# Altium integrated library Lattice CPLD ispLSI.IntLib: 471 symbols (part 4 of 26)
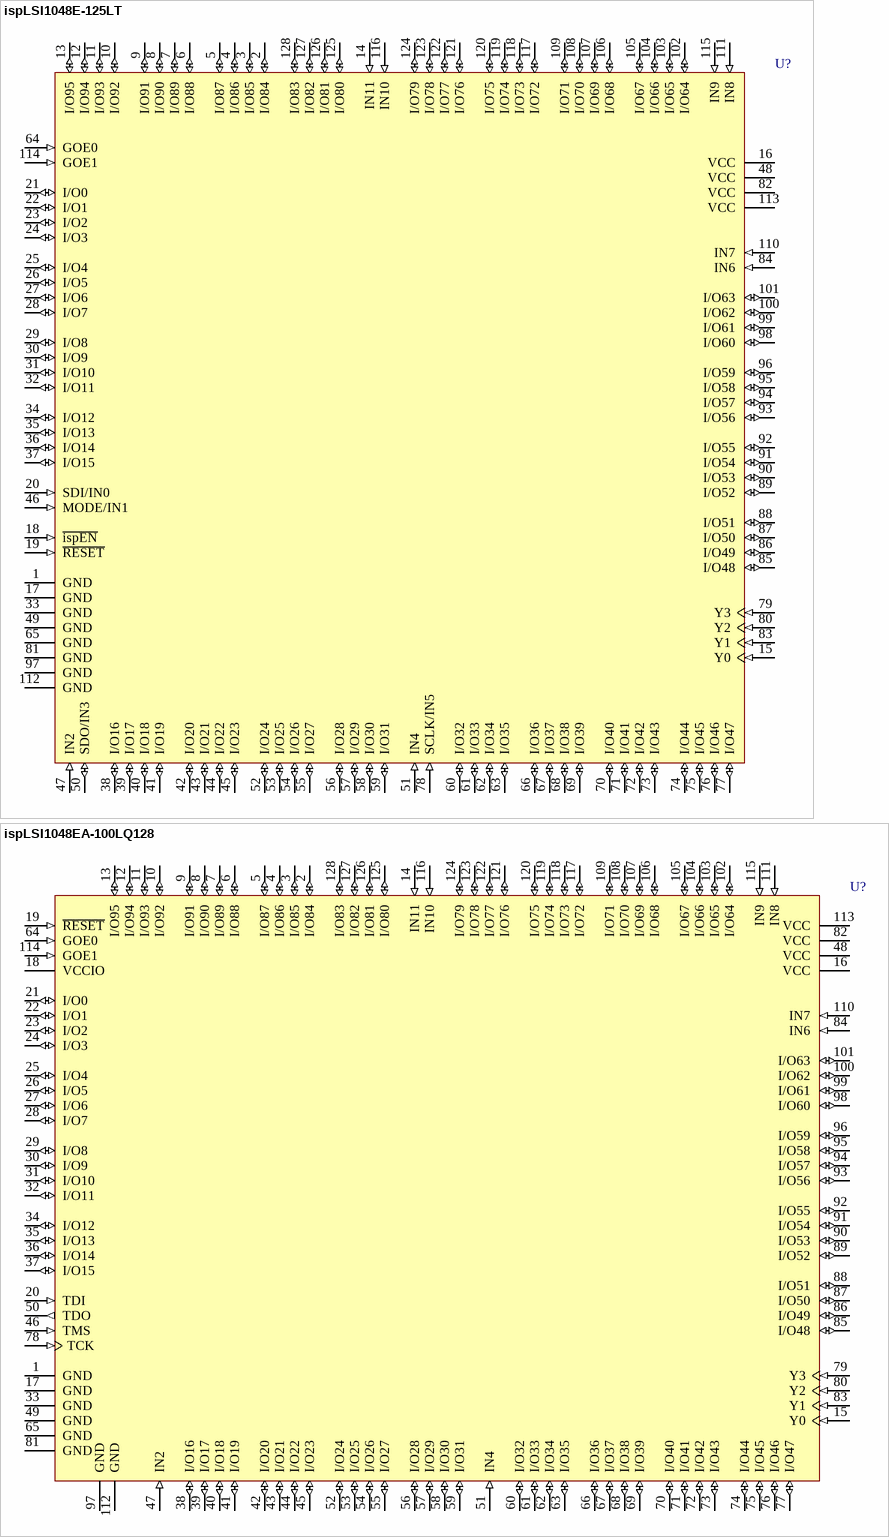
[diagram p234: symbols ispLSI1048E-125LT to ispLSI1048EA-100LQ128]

## ispLSI1048EA-100LQ128
designator U?
In-System Programmable High-Density PLD
footprint PQFP128_N (QFP, 128-Leads, Body 28x28mm, Pitch 0.8mm, IPC Medium Density)
footprint PQFP128_L (QFP, 128-Leads, Body 28x28mm, Pitch 0.8mm, IPC High Density)
footprint PQFP128_M (QFP, 128-Leads, Body 28x28mm, Pitch 0.8mm, IPC Low Density)
3D model 1048EA-PQFP128 (128-Pin Quad Flat Pack 0.8 mm Pitch)
pins: 1 GND (power), 2 I/O84 (io), 3 I/O85 (io), 4 I/O86 (io), 5 I/O87 (io), 6 I/O88 (io), 7 I/O89 (io), 8 I/O90 (io), 9 I/O91 (io), 10 I/O92 (io), 11 I/O93 (io), 12 I/O94 (io), 13 I/O95 (io), 14 IN11 (in), 15 Y0 (in), 16 VCC (power), 17 GND (power), 18 VCCIO (power), 19 ~{RESET} (in), 20 TDI (in), 21 I/O0 (io), 22 I/O1 (io), 23 I/O2 (io), 24 I/O3 (io), 25 I/O4 (io), 26 I/O5 (io), 27 I/O6 (io), 28 I/O7 (io), 29 I/O8 (io), 30 I/O9 (io), 31 I/O10 (io), 32 I/O11 (io), 33 GND (power), 34 I/O12 (io), 35 I/O13 (io), 36 I/O14 (io), 37 I/O15 (io), 38 I/O16 (io), 39 I/O17 (io), 40 I/O18 (io), 41 I/O19 (io), 42 I/O20 (io), 43 I/O21 (io), 44 I/O22 (io), 45 I/O23 (io), 46 TMS (in), 47 IN2 (in), 48 VCC (power), 49 GND (power), 50 TDO (out), 51 IN4 (in), 52 I/O24 (io), 53 I/O25 (io), 54 I/O26 (io), 55 I/O27 (io), 56 I/O28 (io), 57 I/O29 (io), 58 I/O30 (io), 59 I/O31 (io), 60 I/O32 (io), 61 I/O33 (io), 62 I/O34 (io), 63 I/O35 (io), 64 GOE0 (in), 65 GND (power), 66 I/O36 (io), 67 I/O37 (io), 68 I/O38 (io), 69 I/O39 (io), 70 I/O40 (io), 71 I/O41 (io), 72 I/O42 (io), 73 I/O43 (io), 74 I/O44 (io), 75 I/O45 (io), 76 I/O46 (io), 77 I/O47 (io), 78 TCK (in), 79 Y3 (in), 80 Y2 (in), 81 GND (power), 82 VCC (power), 83 Y1 (in), 84 IN6 (in), 85 I/O48 (io), 86 I/O49 (io), 87 I/O50 (io), 88 I/O51 (io), 89 I/O52 (io), 90 I/O53 (io), 91 I/O54 (io), 92 I/O55 (io), 93 I/O56 (io), 94 I/O57 (io), 95 I/O58 (io), 96 I/O59 (io), 97 GND (power), 98 I/O60 (io), 99 I/O61 (io), 100 I/O62 (io), 101 I/O63 (io), 102 I/O64 (io), 103 I/O65 (io), 104 I/O66 (io), 105 I/O67 (io), 106 I/O68 (io), 107 I/O69 (io), 108 I/O70 (io), 109 I/O71 (io), 110 IN7 (in), 111 IN8 (in), 112 GND (power), 113 VCC (power), 114 GOE1 (in), 115 IN9 (in), 116 IN10 (in), 117 I/O72 (io), 118 I/O73 (io), 119 I/O74 (io), 120 I/O75 (io), 121 I/O76 (io), 122 I/O77 (io), 123 I/O78 (io), 124 I/O79 (io), 125 I/O80 (io), 126 I/O81 (io), 127 I/O82 (io), 128 I/O83 (io)

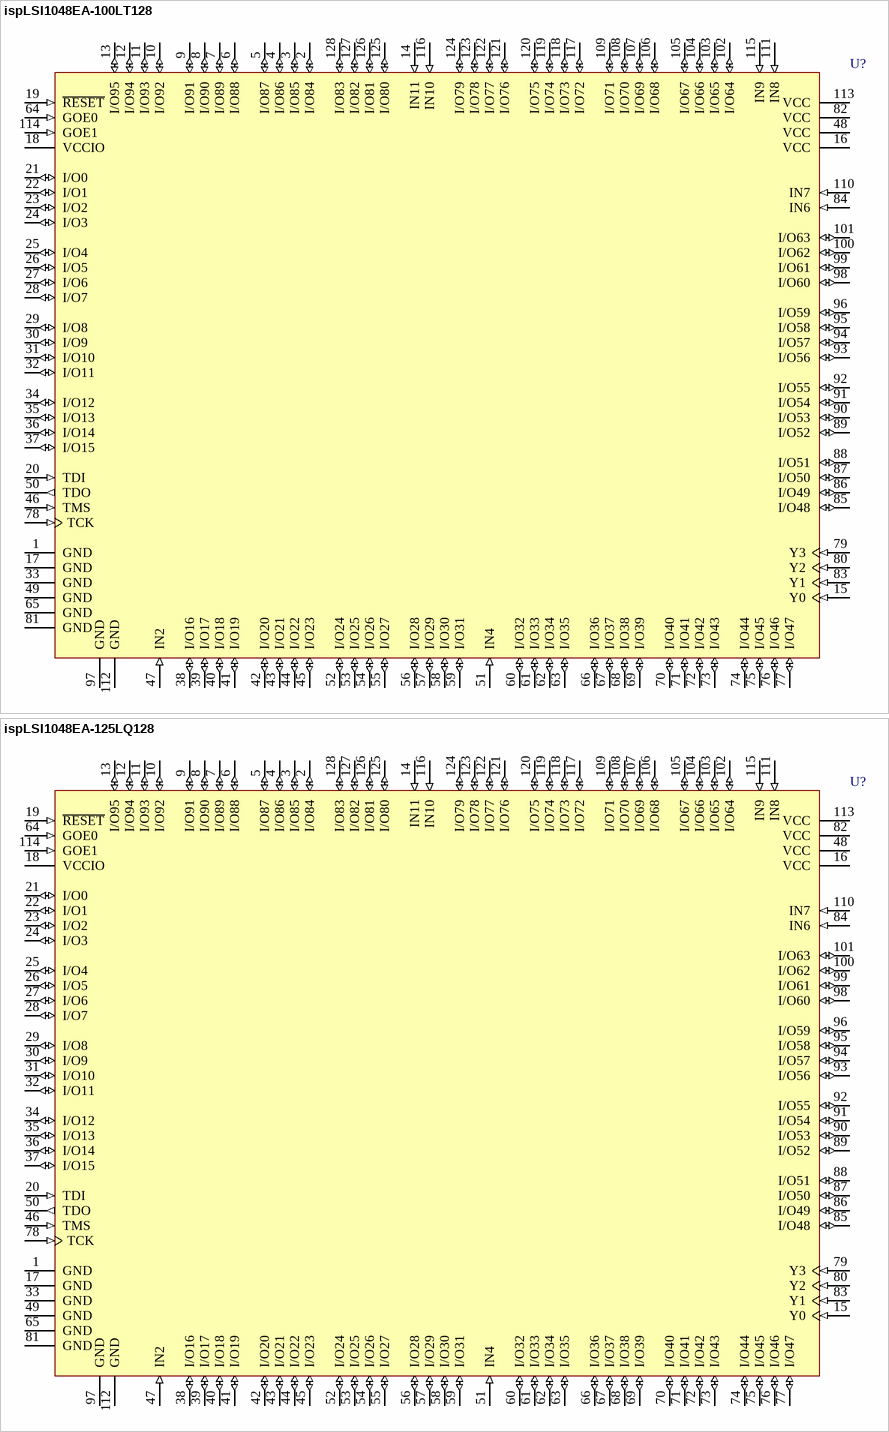
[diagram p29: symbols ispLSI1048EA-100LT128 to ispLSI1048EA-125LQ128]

## ispLSI1048EA-100LT128
designator U?
In-System Programmable High-Density PLD
footprint TQFP128_N (Thin QFP, 128-Leads, Body 14x14mm, Pitch 0.4mm, IPC Medium Density)
footprint TQFP128_L (Thin QFP, 128-Leads, Body 14x14mm, Pitch 0.4mm, IPC High Density)
footprint TQFP128_M (Thin QFP, 128-Leads, Body 14x14mm, Pitch 0.4mm, IPC Low Density)
3D model 1048EA-TQFP128 (128-Pin Thin Quad Flat Pack 0.4 mm Pitch)
pins: 1 GND (power), 2 I/O84 (io), 3 I/O85 (io), 4 I/O86 (io), 5 I/O87 (io), 6 I/O88 (io), 7 I/O89 (io), 8 I/O90 (io), 9 I/O91 (io), 10 I/O92 (io), 11 I/O93 (io), 12 I/O94 (io), 13 I/O95 (io), 14 IN11 (in), 15 Y0 (in), 16 VCC (power), 17 GND (power), 18 VCCIO (power), 19 ~{RESET} (in), 20 TDI (in), 21 I/O0 (io), 22 I/O1 (io), 23 I/O2 (io), 24 I/O3 (io), 25 I/O4 (io), 26 I/O5 (io), 27 I/O6 (io), 28 I/O7 (io), 29 I/O8 (io), 30 I/O9 (io), 31 I/O10 (io), 32 I/O11 (io), 33 GND (power), 34 I/O12 (io), 35 I/O13 (io), 36 I/O14 (io), 37 I/O15 (io), 38 I/O16 (io), 39 I/O17 (io), 40 I/O18 (io), 41 I/O19 (io), 42 I/O20 (io), 43 I/O21 (io), 44 I/O22 (io), 45 I/O23 (io), 46 TMS (in), 47 IN2 (in), 48 VCC (power), 49 GND (power), 50 TDO (out), 51 IN4 (in), 52 I/O24 (io), 53 I/O25 (io), 54 I/O26 (io), 55 I/O27 (io), 56 I/O28 (io), 57 I/O29 (io), 58 I/O30 (io), 59 I/O31 (io), 60 I/O32 (io), 61 I/O33 (io), 62 I/O34 (io), 63 I/O35 (io), 64 GOE0 (in), 65 GND (power), 66 I/O36 (io), 67 I/O37 (io), 68 I/O38 (io), 69 I/O39 (io), 70 I/O40 (io), 71 I/O41 (io), 72 I/O42 (io), 73 I/O43 (io), 74 I/O44 (io), 75 I/O45 (io), 76 I/O46 (io), 77 I/O47 (io), 78 TCK (in), 79 Y3 (in), 80 Y2 (in), 81 GND (power), 82 VCC (power), 83 Y1 (in), 84 IN6 (in), 85 I/O48 (io), 86 I/O49 (io), 87 I/O50 (io), 88 I/O51 (io), 89 I/O52 (io), 90 I/O53 (io), 91 I/O54 (io), 92 I/O55 (io), 93 I/O56 (io), 94 I/O57 (io), 95 I/O58 (io), 96 I/O59 (io), 97 GND (power), 98 I/O60 (io), 99 I/O61 (io), 100 I/O62 (io), 101 I/O63 (io), 102 I/O64 (io), 103 I/O65 (io), 104 I/O66 (io), 105 I/O67 (io), 106 I/O68 (io), 107 I/O69 (io), 108 I/O70 (io), 109 I/O71 (io), 110 IN7 (in), 111 IN8 (in), 112 GND (power), 113 VCC (power), 114 GOE1 (in), 115 IN9 (in), 116 IN10 (in), 117 I/O72 (io), 118 I/O73 (io), 119 I/O74 (io), 120 I/O75 (io), 121 I/O76 (io), 122 I/O77 (io), 123 I/O78 (io), 124 I/O79 (io), 125 I/O80 (io), 126 I/O81 (io), 127 I/O82 (io), 128 I/O83 (io)

## ispLSI1048EA-125LQ128
designator U?
In-System Programmable High-Density PLD
footprint PQFP128_N (QFP, 128-Leads, Body 28x28mm, Pitch 0.8mm, IPC Medium Density)
footprint PQFP128_L (QFP, 128-Leads, Body 28x28mm, Pitch 0.8mm, IPC High Density)
footprint PQFP128_M (QFP, 128-Leads, Body 28x28mm, Pitch 0.8mm, IPC Low Density)
3D model 1048EA-PQFP128 (128-Pin Quad Flat Pack 0.8 mm Pitch)
pins: 1 GND (power), 2 I/O84 (io), 3 I/O85 (io), 4 I/O86 (io), 5 I/O87 (io), 6 I/O88 (io), 7 I/O89 (io), 8 I/O90 (io), 9 I/O91 (io), 10 I/O92 (io), 11 I/O93 (io), 12 I/O94 (io), 13 I/O95 (io), 14 IN11 (in), 15 Y0 (in), 16 VCC (power), 17 GND (power), 18 VCCIO (power), 19 ~{RESET} (in), 20 TDI (in), 21 I/O0 (io), 22 I/O1 (io), 23 I/O2 (io), 24 I/O3 (io), 25 I/O4 (io), 26 I/O5 (io), 27 I/O6 (io), 28 I/O7 (io), 29 I/O8 (io), 30 I/O9 (io), 31 I/O10 (io), 32 I/O11 (io), 33 GND (power), 34 I/O12 (io), 35 I/O13 (io), 36 I/O14 (io), 37 I/O15 (io), 38 I/O16 (io), 39 I/O17 (io), 40 I/O18 (io), 41 I/O19 (io), 42 I/O20 (io), 43 I/O21 (io), 44 I/O22 (io), 45 I/O23 (io), 46 TMS (in), 47 IN2 (in), 48 VCC (power), 49 GND (power), 50 TDO (out), 51 IN4 (in), 52 I/O24 (io), 53 I/O25 (io), 54 I/O26 (io), 55 I/O27 (io), 56 I/O28 (io), 57 I/O29 (io), 58 I/O30 (io), 59 I/O31 (io), 60 I/O32 (io), 61 I/O33 (io), 62 I/O34 (io), 63 I/O35 (io), 64 GOE0 (in), 65 GND (power), 66 I/O36 (io), 67 I/O37 (io), 68 I/O38 (io), 69 I/O39 (io), 70 I/O40 (io), 71 I/O41 (io), 72 I/O42 (io), 73 I/O43 (io), 74 I/O44 (io), 75 I/O45 (io), 76 I/O46 (io), 77 I/O47 (io), 78 TCK (in), 79 Y3 (in), 80 Y2 (in), 81 GND (power), 82 VCC (power), 83 Y1 (in), 84 IN6 (in), 85 I/O48 (io), 86 I/O49 (io), 87 I/O50 (io), 88 I/O51 (io), 89 I/O52 (io), 90 I/O53 (io), 91 I/O54 (io), 92 I/O55 (io), 93 I/O56 (io), 94 I/O57 (io), 95 I/O58 (io), 96 I/O59 (io), 97 GND (power), 98 I/O60 (io), 99 I/O61 (io), 100 I/O62 (io), 101 I/O63 (io), 102 I/O64 (io), 103 I/O65 (io), 104 I/O66 (io), 105 I/O67 (io), 106 I/O68 (io), 107 I/O69 (io), 108 I/O70 (io), 109 I/O71 (io), 110 IN7 (in), 111 IN8 (in), 112 GND (power), 113 VCC (power), 114 GOE1 (in), 115 IN9 (in), 116 IN10 (in), 117 I/O72 (io), 118 I/O73 (io), 119 I/O74 (io), 120 I/O75 (io), 121 I/O76 (io), 122 I/O77 (io), 123 I/O78 (io), 124 I/O79 (io), 125 I/O80 (io), 126 I/O81 (io), 127 I/O82 (io), 128 I/O83 (io)

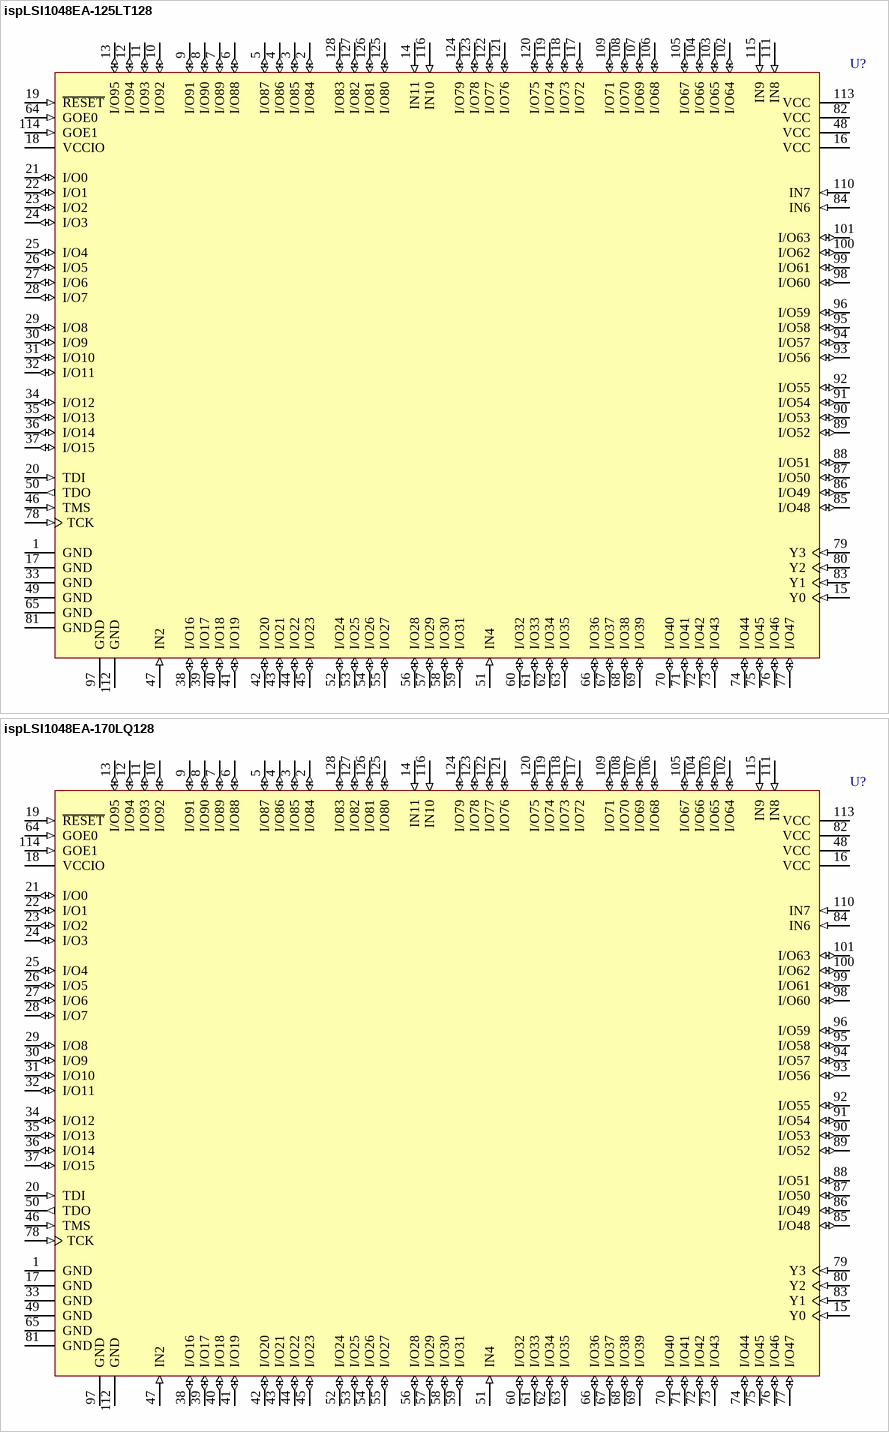
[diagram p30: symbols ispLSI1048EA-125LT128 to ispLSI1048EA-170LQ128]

## ispLSI1048EA-125LT128
designator U?
In-System Programmable High-Density PLD
footprint TQFP128_N (Thin QFP, 128-Leads, Body 14x14mm, Pitch 0.4mm, IPC Medium Density)
footprint TQFP128_L (Thin QFP, 128-Leads, Body 14x14mm, Pitch 0.4mm, IPC High Density)
footprint TQFP128_M (Thin QFP, 128-Leads, Body 14x14mm, Pitch 0.4mm, IPC Low Density)
3D model 1048EA-TQFP128 (128-Pin Thin Quad Flat Pack 0.4 mm Pitch)
pins: 1 GND (power), 2 I/O84 (io), 3 I/O85 (io), 4 I/O86 (io), 5 I/O87 (io), 6 I/O88 (io), 7 I/O89 (io), 8 I/O90 (io), 9 I/O91 (io), 10 I/O92 (io), 11 I/O93 (io), 12 I/O94 (io), 13 I/O95 (io), 14 IN11 (in), 15 Y0 (in), 16 VCC (power), 17 GND (power), 18 VCCIO (power), 19 ~{RESET} (in), 20 TDI (in), 21 I/O0 (io), 22 I/O1 (io), 23 I/O2 (io), 24 I/O3 (io), 25 I/O4 (io), 26 I/O5 (io), 27 I/O6 (io), 28 I/O7 (io), 29 I/O8 (io), 30 I/O9 (io), 31 I/O10 (io), 32 I/O11 (io), 33 GND (power), 34 I/O12 (io), 35 I/O13 (io), 36 I/O14 (io), 37 I/O15 (io), 38 I/O16 (io), 39 I/O17 (io), 40 I/O18 (io), 41 I/O19 (io), 42 I/O20 (io), 43 I/O21 (io), 44 I/O22 (io), 45 I/O23 (io), 46 TMS (in), 47 IN2 (in), 48 VCC (power), 49 GND (power), 50 TDO (out), 51 IN4 (in), 52 I/O24 (io), 53 I/O25 (io), 54 I/O26 (io), 55 I/O27 (io), 56 I/O28 (io), 57 I/O29 (io), 58 I/O30 (io), 59 I/O31 (io), 60 I/O32 (io), 61 I/O33 (io), 62 I/O34 (io), 63 I/O35 (io), 64 GOE0 (in), 65 GND (power), 66 I/O36 (io), 67 I/O37 (io), 68 I/O38 (io), 69 I/O39 (io), 70 I/O40 (io), 71 I/O41 (io), 72 I/O42 (io), 73 I/O43 (io), 74 I/O44 (io), 75 I/O45 (io), 76 I/O46 (io), 77 I/O47 (io), 78 TCK (in), 79 Y3 (in), 80 Y2 (in), 81 GND (power), 82 VCC (power), 83 Y1 (in), 84 IN6 (in), 85 I/O48 (io), 86 I/O49 (io), 87 I/O50 (io), 88 I/O51 (io), 89 I/O52 (io), 90 I/O53 (io), 91 I/O54 (io), 92 I/O55 (io), 93 I/O56 (io), 94 I/O57 (io), 95 I/O58 (io), 96 I/O59 (io), 97 GND (power), 98 I/O60 (io), 99 I/O61 (io), 100 I/O62 (io), 101 I/O63 (io), 102 I/O64 (io), 103 I/O65 (io), 104 I/O66 (io), 105 I/O67 (io), 106 I/O68 (io), 107 I/O69 (io), 108 I/O70 (io), 109 I/O71 (io), 110 IN7 (in), 111 IN8 (in), 112 GND (power), 113 VCC (power), 114 GOE1 (in), 115 IN9 (in), 116 IN10 (in), 117 I/O72 (io), 118 I/O73 (io), 119 I/O74 (io), 120 I/O75 (io), 121 I/O76 (io), 122 I/O77 (io), 123 I/O78 (io), 124 I/O79 (io), 125 I/O80 (io), 126 I/O81 (io), 127 I/O82 (io), 128 I/O83 (io)

## ispLSI1048EA-170LQ128
designator U?
In-System Programmable High-Density PLD
footprint PQFP128_N (QFP, 128-Leads, Body 28x28mm, Pitch 0.8mm, IPC Medium Density)
footprint PQFP128_L (QFP, 128-Leads, Body 28x28mm, Pitch 0.8mm, IPC High Density)
footprint PQFP128_M (QFP, 128-Leads, Body 28x28mm, Pitch 0.8mm, IPC Low Density)
3D model 1048EA-PQFP128 (128-Pin Quad Flat Pack 0.8 mm Pitch)
pins: 1 GND (power), 2 I/O84 (io), 3 I/O85 (io), 4 I/O86 (io), 5 I/O87 (io), 6 I/O88 (io), 7 I/O89 (io), 8 I/O90 (io), 9 I/O91 (io), 10 I/O92 (io), 11 I/O93 (io), 12 I/O94 (io), 13 I/O95 (io), 14 IN11 (in), 15 Y0 (in), 16 VCC (power), 17 GND (power), 18 VCCIO (power), 19 ~{RESET} (in), 20 TDI (in), 21 I/O0 (io), 22 I/O1 (io), 23 I/O2 (io), 24 I/O3 (io), 25 I/O4 (io), 26 I/O5 (io), 27 I/O6 (io), 28 I/O7 (io), 29 I/O8 (io), 30 I/O9 (io), 31 I/O10 (io), 32 I/O11 (io), 33 GND (power), 34 I/O12 (io), 35 I/O13 (io), 36 I/O14 (io), 37 I/O15 (io), 38 I/O16 (io), 39 I/O17 (io), 40 I/O18 (io), 41 I/O19 (io), 42 I/O20 (io), 43 I/O21 (io), 44 I/O22 (io), 45 I/O23 (io), 46 TMS (in), 47 IN2 (in), 48 VCC (power), 49 GND (power), 50 TDO (out), 51 IN4 (in), 52 I/O24 (io), 53 I/O25 (io), 54 I/O26 (io), 55 I/O27 (io), 56 I/O28 (io), 57 I/O29 (io), 58 I/O30 (io), 59 I/O31 (io), 60 I/O32 (io), 61 I/O33 (io), 62 I/O34 (io), 63 I/O35 (io), 64 GOE0 (in), 65 GND (power), 66 I/O36 (io), 67 I/O37 (io), 68 I/O38 (io), 69 I/O39 (io), 70 I/O40 (io), 71 I/O41 (io), 72 I/O42 (io), 73 I/O43 (io), 74 I/O44 (io), 75 I/O45 (io), 76 I/O46 (io), 77 I/O47 (io), 78 TCK (in), 79 Y3 (in), 80 Y2 (in), 81 GND (power), 82 VCC (power), 83 Y1 (in), 84 IN6 (in), 85 I/O48 (io), 86 I/O49 (io), 87 I/O50 (io), 88 I/O51 (io), 89 I/O52 (io), 90 I/O53 (io), 91 I/O54 (io), 92 I/O55 (io), 93 I/O56 (io), 94 I/O57 (io), 95 I/O58 (io), 96 I/O59 (io), 97 GND (power), 98 I/O60 (io), 99 I/O61 (io), 100 I/O62 (io), 101 I/O63 (io), 102 I/O64 (io), 103 I/O65 (io), 104 I/O66 (io), 105 I/O67 (io), 106 I/O68 (io), 107 I/O69 (io), 108 I/O70 (io), 109 I/O71 (io), 110 IN7 (in), 111 IN8 (in), 112 GND (power), 113 VCC (power), 114 GOE1 (in), 115 IN9 (in), 116 IN10 (in), 117 I/O72 (io), 118 I/O73 (io), 119 I/O74 (io), 120 I/O75 (io), 121 I/O76 (io), 122 I/O77 (io), 123 I/O78 (io), 124 I/O79 (io), 125 I/O80 (io), 126 I/O81 (io), 127 I/O82 (io), 128 I/O83 (io)

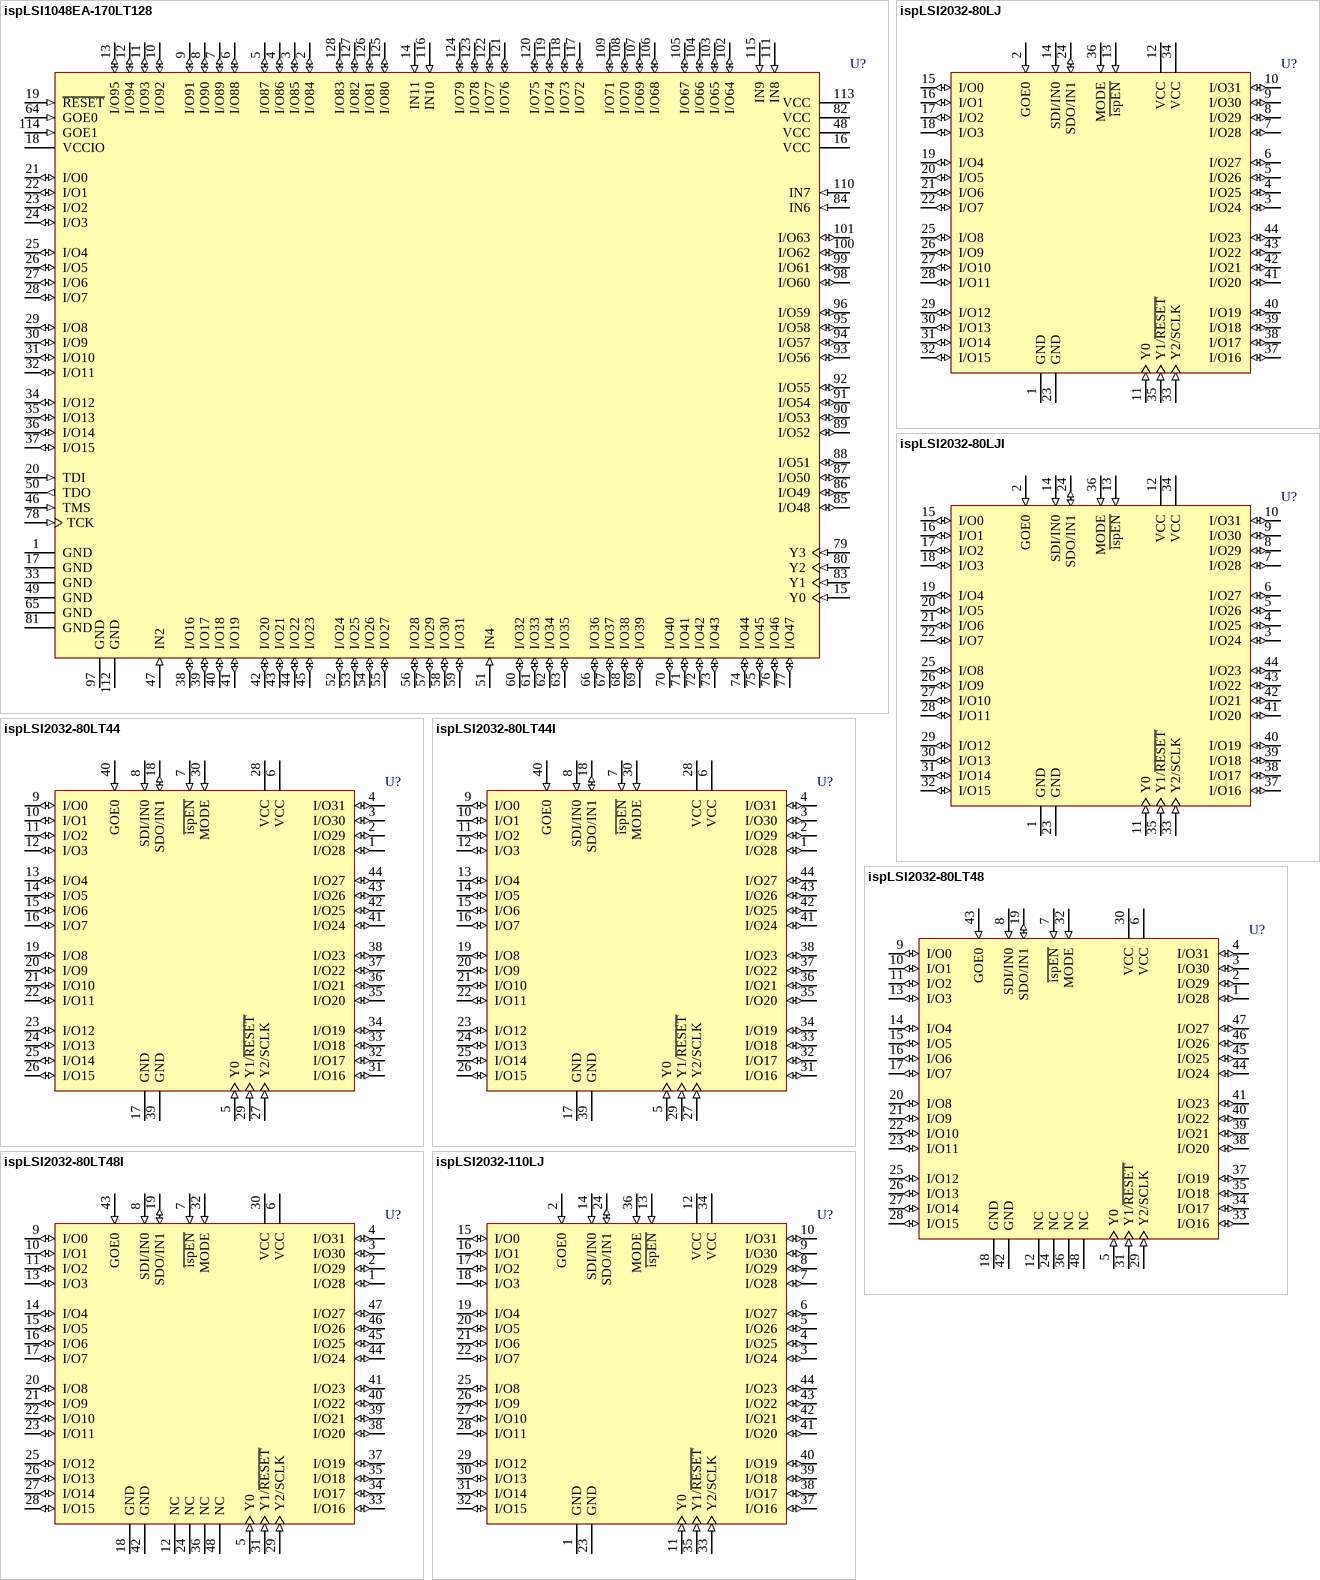
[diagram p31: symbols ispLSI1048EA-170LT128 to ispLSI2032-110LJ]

## ispLSI1048EA-170LT128
designator U?
In-System Programmable High-Density PLD
footprint TQFP128_N (Thin QFP, 128-Leads, Body 14x14mm, Pitch 0.4mm, IPC Medium Density)
footprint TQFP128_L (Thin QFP, 128-Leads, Body 14x14mm, Pitch 0.4mm, IPC High Density)
footprint TQFP128_M (Thin QFP, 128-Leads, Body 14x14mm, Pitch 0.4mm, IPC Low Density)
3D model 1048EA-TQFP128 (128-Pin Thin Quad Flat Pack 0.4 mm Pitch)
pins: 1 GND (power), 2 I/O84 (io), 3 I/O85 (io), 4 I/O86 (io), 5 I/O87 (io), 6 I/O88 (io), 7 I/O89 (io), 8 I/O90 (io), 9 I/O91 (io), 10 I/O92 (io), 11 I/O93 (io), 12 I/O94 (io), 13 I/O95 (io), 14 IN11 (in), 15 Y0 (in), 16 VCC (power), 17 GND (power), 18 VCCIO (power), 19 ~{RESET} (in), 20 TDI (in), 21 I/O0 (io), 22 I/O1 (io), 23 I/O2 (io), 24 I/O3 (io), 25 I/O4 (io), 26 I/O5 (io), 27 I/O6 (io), 28 I/O7 (io), 29 I/O8 (io), 30 I/O9 (io), 31 I/O10 (io), 32 I/O11 (io), 33 GND (power), 34 I/O12 (io), 35 I/O13 (io), 36 I/O14 (io), 37 I/O15 (io), 38 I/O16 (io), 39 I/O17 (io), 40 I/O18 (io), 41 I/O19 (io), 42 I/O20 (io), 43 I/O21 (io), 44 I/O22 (io), 45 I/O23 (io), 46 TMS (in), 47 IN2 (in), 48 VCC (power), 49 GND (power), 50 TDO (out), 51 IN4 (in), 52 I/O24 (io), 53 I/O25 (io), 54 I/O26 (io), 55 I/O27 (io), 56 I/O28 (io), 57 I/O29 (io), 58 I/O30 (io), 59 I/O31 (io), 60 I/O32 (io), 61 I/O33 (io), 62 I/O34 (io), 63 I/O35 (io), 64 GOE0 (in), 65 GND (power), 66 I/O36 (io), 67 I/O37 (io), 68 I/O38 (io), 69 I/O39 (io), 70 I/O40 (io), 71 I/O41 (io), 72 I/O42 (io), 73 I/O43 (io), 74 I/O44 (io), 75 I/O45 (io), 76 I/O46 (io), 77 I/O47 (io), 78 TCK (in), 79 Y3 (in), 80 Y2 (in), 81 GND (power), 82 VCC (power), 83 Y1 (in), 84 IN6 (in), 85 I/O48 (io), 86 I/O49 (io), 87 I/O50 (io), 88 I/O51 (io), 89 I/O52 (io), 90 I/O53 (io), 91 I/O54 (io), 92 I/O55 (io), 93 I/O56 (io), 94 I/O57 (io), 95 I/O58 (io), 96 I/O59 (io), 97 GND (power), 98 I/O60 (io), 99 I/O61 (io), 100 I/O62 (io), 101 I/O63 (io), 102 I/O64 (io), 103 I/O65 (io), 104 I/O66 (io), 105 I/O67 (io), 106 I/O68 (io), 107 I/O69 (io), 108 I/O70 (io), 109 I/O71 (io), 110 IN7 (in), 111 IN8 (in), 112 GND (power), 113 VCC (power), 114 GOE1 (in), 115 IN9 (in), 116 IN10 (in), 117 I/O72 (io), 118 I/O73 (io), 119 I/O74 (io), 120 I/O75 (io), 121 I/O76 (io), 122 I/O77 (io), 123 I/O78 (io), 124 I/O79 (io), 125 I/O80 (io), 126 I/O81 (io), 127 I/O82 (io), 128 I/O83 (io)

## ispLSI2032-80LJ
designator U?
In-System Programmable High-Density PLD; Note: Pins 14, 24 and 33 have dual function capability.
footprint PLCC44_N (Leaded Chip Carrier, 44-Leads, Body 16.6x16.6mm, Pitch 1.27mm, IPC Medium Density)
footprint PLCC44_L (Leaded Chip Carrier, 44-Leads, Body 16.6x16.6mm, Pitch 1.27mm, IPC High Density)
footprint PLCC44_M (Leaded Chip Carrier, 44-Leads, Body 16.6x16.6mm, Pitch 1.27mm, IPC Low Density)
3D model 2032-PLCC44 (44-Pin Leaded Chip Carrier 1.27 mm Pitch)
pins: 1 GND (power), 2 GOE0 (in), 3 I/O24 (io), 4 I/O25 (io), 5 I/O26 (io), 6 I/O27 (io), 7 I/O28 (io), 8 I/O29 (io), 9 I/O30 (io), 10 I/O31 (io), 11 Y0 (in), 12 VCC (power), 13 ~{ispEN} (in), 14 SDI/IN0 (in), 15 I/O0 (io), 16 I/O1 (io), 17 I/O2 (io), 18 I/O3 (io), 19 I/O4 (io), 20 I/O5 (io), 21 I/O6 (io), 22 I/O7 (io), 23 GND (power), 24 SDO/IN1 (io), 25 I/O8 (io), 26 I/O9 (io), 27 I/O10 (io), 28 I/O11 (io), 29 I/O12 (io), 30 I/O13 (io), 31 I/O14 (io), 32 I/O15 (io), 33 Y2/SCLK (in), 34 VCC (power), 35 Y1/~{RESET} (in), 36 MODE (in), 37 I/O16 (io), 38 I/O17 (io), 39 I/O18 (io), 40 I/O19 (io), 41 I/O20 (io), 42 I/O21 (io), 43 I/O22 (io), 44 I/O23 (io)

## ispLSI2032-80LJI
designator U?
In-System Programmable High-Density PLD; Note: Pins 14, 24 and 33 have dual function capability.
footprint PLCC44_N (Leaded Chip Carrier, 44-Leads, Body 16.6x16.6mm, Pitch 1.27mm, IPC Medium Density)
footprint PLCC44_L (Leaded Chip Carrier, 44-Leads, Body 16.6x16.6mm, Pitch 1.27mm, IPC High Density)
footprint PLCC44_M (Leaded Chip Carrier, 44-Leads, Body 16.6x16.6mm, Pitch 1.27mm, IPC Low Density)
3D model 2032-PLCC44 (44-Pin Leaded Chip Carrier 1.27 mm Pitch)
pins: 1 GND (power), 2 GOE0 (in), 3 I/O24 (io), 4 I/O25 (io), 5 I/O26 (io), 6 I/O27 (io), 7 I/O28 (io), 8 I/O29 (io), 9 I/O30 (io), 10 I/O31 (io), 11 Y0 (in), 12 VCC (power), 13 ~{ispEN} (in), 14 SDI/IN0 (in), 15 I/O0 (io), 16 I/O1 (io), 17 I/O2 (io), 18 I/O3 (io), 19 I/O4 (io), 20 I/O5 (io), 21 I/O6 (io), 22 I/O7 (io), 23 GND (power), 24 SDO/IN1 (io), 25 I/O8 (io), 26 I/O9 (io), 27 I/O10 (io), 28 I/O11 (io), 29 I/O12 (io), 30 I/O13 (io), 31 I/O14 (io), 32 I/O15 (io), 33 Y2/SCLK (in), 34 VCC (power), 35 Y1/~{RESET} (in), 36 MODE (in), 37 I/O16 (io), 38 I/O17 (io), 39 I/O18 (io), 40 I/O19 (io), 41 I/O20 (io), 42 I/O21 (io), 43 I/O22 (io), 44 I/O23 (io)

## ispLSI2032-80LT44
designator U?
In-System Programmable High-Density PLD; Note: Pins 8, 18 and 27 have dual function capability.
footprint TQFP44_N (Thin QFP, 44-Leads, Body 10x10mm, Pitch 0.8mm, IPC Medium Density)
footprint TQFP44_L (Thin QFP, 44-Leads, Body 10x10mm, Pitch 0.8mm, IPC High Density)
footprint TQFP44_M (Thin QFP, 44-Leads, Body 10x10mm, Pitch 0.8mm, IPC Low Density)
3D model 2032-TQFP44 (44-Pin Thin Quad Flat Pack 0.8 mm Pitch)
pins: 1 I/O28 (io), 2 I/O29 (io), 3 I/O30 (io), 4 I/O31 (io), 5 Y0 (in), 6 VCC (power), 7 ~{ispEN} (in), 8 SDI/IN0 (in), 9 I/O0 (io), 10 I/O1 (io), 11 I/O2 (io), 12 I/O3 (io), 13 I/O4 (io), 14 I/O5 (io), 15 I/O6 (io), 16 I/O7 (io), 17 GND (power), 18 SDO/IN1 (io), 19 I/O8 (io), 20 I/O9 (io), 21 I/O10 (io), 22 I/O11 (io), 23 I/O12 (io), 24 I/O13 (io), 25 I/O14 (io), 26 I/O15 (io), 27 Y2/SCLK (in), 28 VCC (power), 29 Y1/~{RESET} (in), 30 MODE (in), 31 I/O16 (io), 32 I/O17 (io), 33 I/O18 (io), 34 I/O19 (io), 35 I/O20 (io), 36 I/O21 (io), 37 I/O22 (io), 38 I/O23 (io), 39 GND (power), 40 GOE0 (in), 41 I/O24 (io), 42 I/O25 (io), 43 I/O26 (io), 44 I/O27 (io)

## ispLSI2032-80LT44I
designator U?
In-System Programmable High-Density PLD; Note: Pins 8, 18 and 27 have dual function capability.
footprint TQFP44_N (Thin QFP, 44-Leads, Body 10x10mm, Pitch 0.8mm, IPC Medium Density)
footprint TQFP44_L (Thin QFP, 44-Leads, Body 10x10mm, Pitch 0.8mm, IPC High Density)
footprint TQFP44_M (Thin QFP, 44-Leads, Body 10x10mm, Pitch 0.8mm, IPC Low Density)
3D model 2032-TQFP44 (44-Pin Thin Quad Flat Pack 0.8 mm Pitch)
pins: 1 I/O28 (io), 2 I/O29 (io), 3 I/O30 (io), 4 I/O31 (io), 5 Y0 (in), 6 VCC (power), 7 ~{ispEN} (in), 8 SDI/IN0 (in), 9 I/O0 (io), 10 I/O1 (io), 11 I/O2 (io), 12 I/O3 (io), 13 I/O4 (io), 14 I/O5 (io), 15 I/O6 (io), 16 I/O7 (io), 17 GND (power), 18 SDO/IN1 (io), 19 I/O8 (io), 20 I/O9 (io), 21 I/O10 (io), 22 I/O11 (io), 23 I/O12 (io), 24 I/O13 (io), 25 I/O14 (io), 26 I/O15 (io), 27 Y2/SCLK (in), 28 VCC (power), 29 Y1/~{RESET} (in), 30 MODE (in), 31 I/O16 (io), 32 I/O17 (io), 33 I/O18 (io), 34 I/O19 (io), 35 I/O20 (io), 36 I/O21 (io), 37 I/O22 (io), 38 I/O23 (io), 39 GND (power), 40 GOE0 (in), 41 I/O24 (io), 42 I/O25 (io), 43 I/O26 (io), 44 I/O27 (io)

## ispLSI2032-80LT48
designator U?
In-System Programmable High-Density PLD; Note: Pins 8, 19 and 29 have dual function capability.
footprint TQFP48_N (Thin QFP, 48-Leads, Body 7x7mm, Pitch 0.5mm, IPC Medium Density)
footprint TQFP48_L (Thin QFP, 48-Leads, Body 7x7mm, Pitch 0.5mm, IPC High Density)
footprint TQFP48_M (Thin QFP, 48-Leads, Body 7x7mm, Pitch 0.5mm, IPC Low Density)
3D model 2032-TQFP48 (48-Pin Thin Quad Flat Pack 0.5 mm Pitch)
pins: 1 I/O28 (io), 2 I/O29 (io), 3 I/O30 (io), 4 I/O31 (io), 5 Y0 (in), 6 VCC (power), 7 ~{ispEN} (in), 8 SDI/IN0 (in), 9 I/O0 (io), 10 I/O1 (io), 11 I/O2 (io), 12 NC, 13 I/O3 (io), 14 I/O4 (io), 15 I/O5 (io), 16 I/O6 (io), 17 I/O7 (io), 18 GND (power), 19 SDO/IN1 (io), 20 I/O8 (io), 21 I/O9 (io), 22 I/O10 (io), 23 I/O11 (io), 24 NC, 25 I/O12 (io), 26 I/O13 (io), 27 I/O14 (io), 28 I/O15 (io), 29 Y2/SCLK (in), 30 VCC (power), 31 Y1/~{RESET} (in), 32 MODE (in), 33 I/O16 (io), 34 I/O17 (io), 35 I/O18 (io), 36 NC, 37 I/O19 (io), 38 I/O20 (io), 39 I/O21 (io), 40 I/O22 (io), 41 I/O23 (io), 42 GND (power), 43 GOE0 (in), 44 I/O24 (io), 45 I/O25 (io), 46 I/O26 (io), 47 I/O27 (io), 48 NC

## ispLSI2032-80LT48I
designator U?
In-System Programmable High-Density PLD; Note: Pins 8, 19 and 29 have dual function capability.
footprint TQFP48_N (Thin QFP, 48-Leads, Body 7x7mm, Pitch 0.5mm, IPC Medium Density)
footprint TQFP48_L (Thin QFP, 48-Leads, Body 7x7mm, Pitch 0.5mm, IPC High Density)
footprint TQFP48_M (Thin QFP, 48-Leads, Body 7x7mm, Pitch 0.5mm, IPC Low Density)
3D model 2032-TQFP48 (48-Pin Thin Quad Flat Pack 0.5 mm Pitch)
pins: 1 I/O28 (io), 2 I/O29 (io), 3 I/O30 (io), 4 I/O31 (io), 5 Y0 (in), 6 VCC (power), 7 ~{ispEN} (in), 8 SDI/IN0 (in), 9 I/O0 (io), 10 I/O1 (io), 11 I/O2 (io), 12 NC, 13 I/O3 (io), 14 I/O4 (io), 15 I/O5 (io), 16 I/O6 (io), 17 I/O7 (io), 18 GND (power), 19 SDO/IN1 (io), 20 I/O8 (io), 21 I/O9 (io), 22 I/O10 (io), 23 I/O11 (io), 24 NC, 25 I/O12 (io), 26 I/O13 (io), 27 I/O14 (io), 28 I/O15 (io), 29 Y2/SCLK (in), 30 VCC (power), 31 Y1/~{RESET} (in), 32 MODE (in), 33 I/O16 (io), 34 I/O17 (io), 35 I/O18 (io), 36 NC, 37 I/O19 (io), 38 I/O20 (io), 39 I/O21 (io), 40 I/O22 (io), 41 I/O23 (io), 42 GND (power), 43 GOE0 (in), 44 I/O24 (io), 45 I/O25 (io), 46 I/O26 (io), 47 I/O27 (io), 48 NC

## ispLSI2032-110LJ
designator U?
In-System Programmable High-Density PLD; Note: Pins 14, 24 and 33 have dual function capability.
footprint PLCC44_N (Leaded Chip Carrier, 44-Leads, Body 16.6x16.6mm, Pitch 1.27mm, IPC Medium Density)
footprint PLCC44_L (Leaded Chip Carrier, 44-Leads, Body 16.6x16.6mm, Pitch 1.27mm, IPC High Density)
footprint PLCC44_M (Leaded Chip Carrier, 44-Leads, Body 16.6x16.6mm, Pitch 1.27mm, IPC Low Density)
3D model 2032-PLCC44 (44-Pin Leaded Chip Carrier 1.27 mm Pitch)
pins: 1 GND (power), 2 GOE0 (in), 3 I/O24 (io), 4 I/O25 (io), 5 I/O26 (io), 6 I/O27 (io), 7 I/O28 (io), 8 I/O29 (io), 9 I/O30 (io), 10 I/O31 (io), 11 Y0 (in), 12 VCC (power), 13 ~{ispEN} (in), 14 SDI/IN0 (in), 15 I/O0 (io), 16 I/O1 (io), 17 I/O2 (io), 18 I/O3 (io), 19 I/O4 (io), 20 I/O5 (io), 21 I/O6 (io), 22 I/O7 (io), 23 GND (power), 24 SDO/IN1 (io), 25 I/O8 (io), 26 I/O9 (io), 27 I/O10 (io), 28 I/O11 (io), 29 I/O12 (io), 30 I/O13 (io), 31 I/O14 (io), 32 I/O15 (io), 33 Y2/SCLK (in), 34 VCC (power), 35 Y1/~{RESET} (in), 36 MODE (in), 37 I/O16 (io), 38 I/O17 (io), 39 I/O18 (io), 40 I/O19 (io), 41 I/O20 (io), 42 I/O21 (io), 43 I/O22 (io), 44 I/O23 (io)

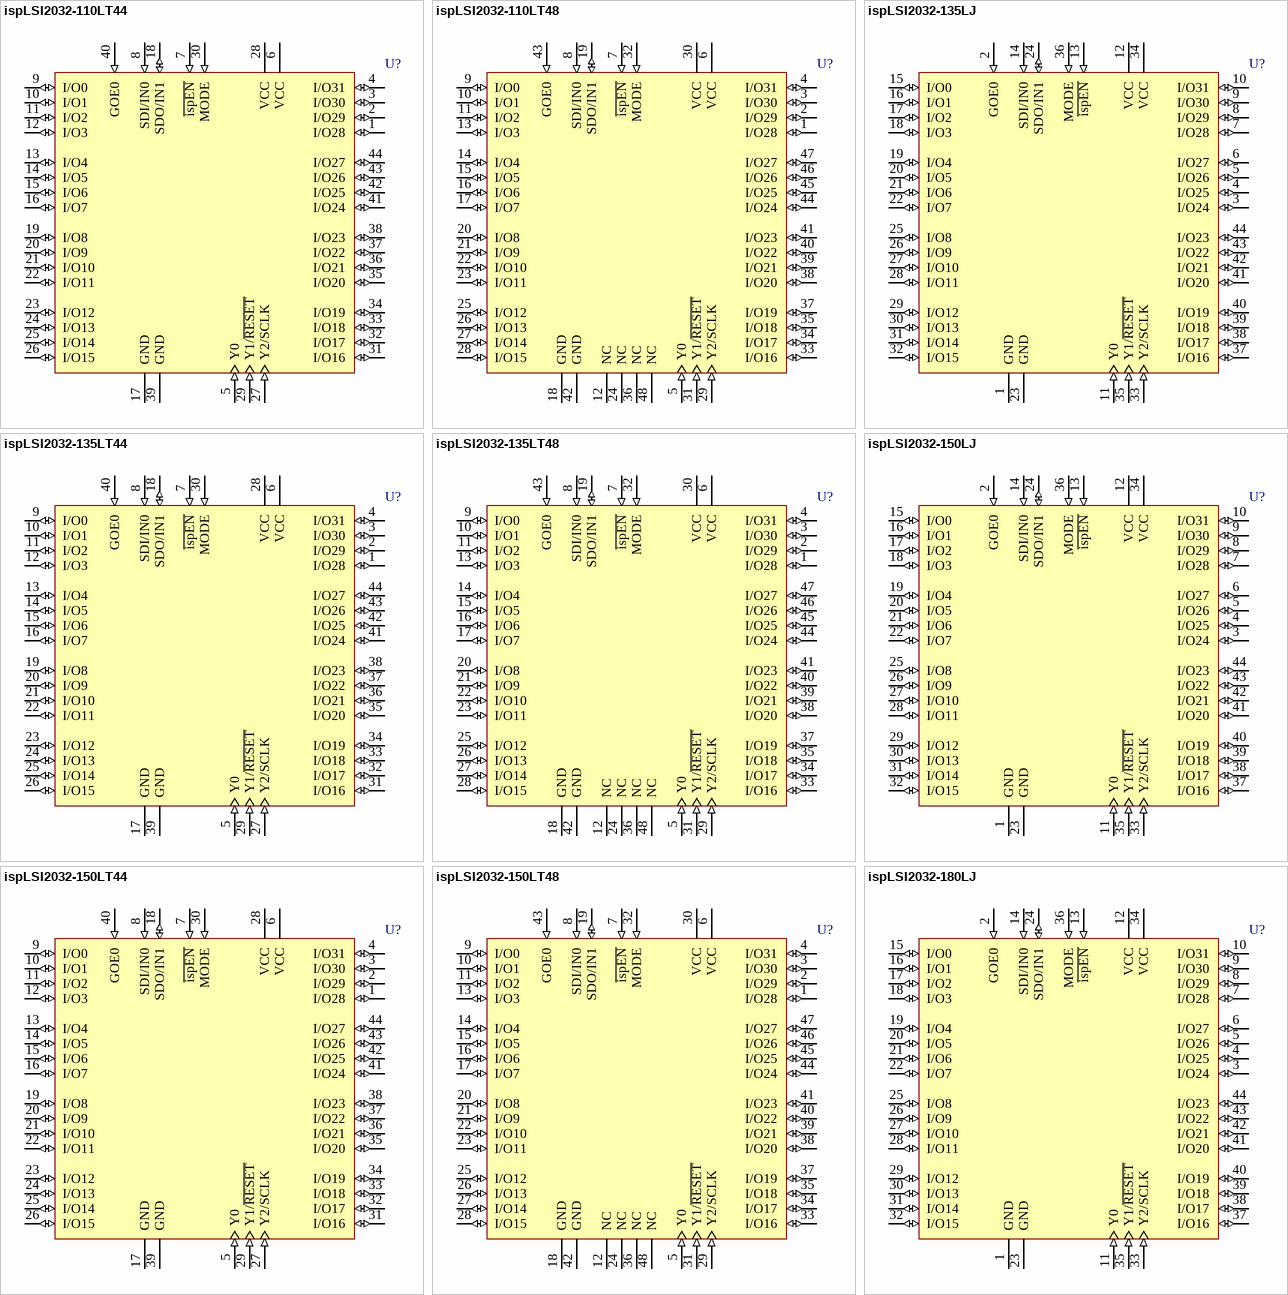
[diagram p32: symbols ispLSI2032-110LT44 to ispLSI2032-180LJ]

## ispLSI2032-110LT44
designator U?
In-System Programmable High-Density PLD; Note: Pins 8, 18 and 27 have dual function capability.
footprint TQFP44_N (Thin QFP, 44-Leads, Body 10x10mm, Pitch 0.8mm, IPC Medium Density)
footprint TQFP44_L (Thin QFP, 44-Leads, Body 10x10mm, Pitch 0.8mm, IPC High Density)
footprint TQFP44_M (Thin QFP, 44-Leads, Body 10x10mm, Pitch 0.8mm, IPC Low Density)
3D model 2032-TQFP44 (44-Pin Thin Quad Flat Pack 0.8 mm Pitch)
pins: 1 I/O28 (io), 2 I/O29 (io), 3 I/O30 (io), 4 I/O31 (io), 5 Y0 (in), 6 VCC (power), 7 ~{ispEN} (in), 8 SDI/IN0 (in), 9 I/O0 (io), 10 I/O1 (io), 11 I/O2 (io), 12 I/O3 (io), 13 I/O4 (io), 14 I/O5 (io), 15 I/O6 (io), 16 I/O7 (io), 17 GND (power), 18 SDO/IN1 (io), 19 I/O8 (io), 20 I/O9 (io), 21 I/O10 (io), 22 I/O11 (io), 23 I/O12 (io), 24 I/O13 (io), 25 I/O14 (io), 26 I/O15 (io), 27 Y2/SCLK (in), 28 VCC (power), 29 Y1/~{RESET} (in), 30 MODE (in), 31 I/O16 (io), 32 I/O17 (io), 33 I/O18 (io), 34 I/O19 (io), 35 I/O20 (io), 36 I/O21 (io), 37 I/O22 (io), 38 I/O23 (io), 39 GND (power), 40 GOE0 (in), 41 I/O24 (io), 42 I/O25 (io), 43 I/O26 (io), 44 I/O27 (io)

## ispLSI2032-110LT48
designator U?
In-System Programmable High-Density PLD; Note: Pins 8, 19 and 29 have dual function capability.
footprint TQFP48_N (Thin QFP, 48-Leads, Body 7x7mm, Pitch 0.5mm, IPC Medium Density)
footprint TQFP48_L (Thin QFP, 48-Leads, Body 7x7mm, Pitch 0.5mm, IPC High Density)
footprint TQFP48_M (Thin QFP, 48-Leads, Body 7x7mm, Pitch 0.5mm, IPC Low Density)
3D model 2032-TQFP48 (48-Pin Thin Quad Flat Pack 0.5 mm Pitch)
pins: 1 I/O28 (io), 2 I/O29 (io), 3 I/O30 (io), 4 I/O31 (io), 5 Y0 (in), 6 VCC (power), 7 ~{ispEN} (in), 8 SDI/IN0 (in), 9 I/O0 (io), 10 I/O1 (io), 11 I/O2 (io), 12 NC, 13 I/O3 (io), 14 I/O4 (io), 15 I/O5 (io), 16 I/O6 (io), 17 I/O7 (io), 18 GND (power), 19 SDO/IN1 (io), 20 I/O8 (io), 21 I/O9 (io), 22 I/O10 (io), 23 I/O11 (io), 24 NC, 25 I/O12 (io), 26 I/O13 (io), 27 I/O14 (io), 28 I/O15 (io), 29 Y2/SCLK (in), 30 VCC (power), 31 Y1/~{RESET} (in), 32 MODE (in), 33 I/O16 (io), 34 I/O17 (io), 35 I/O18 (io), 36 NC, 37 I/O19 (io), 38 I/O20 (io), 39 I/O21 (io), 40 I/O22 (io), 41 I/O23 (io), 42 GND (power), 43 GOE0 (in), 44 I/O24 (io), 45 I/O25 (io), 46 I/O26 (io), 47 I/O27 (io), 48 NC

## ispLSI2032-135LJ
designator U?
In-System Programmable High-Density PLD; Note: Pins 14, 24 and 33 have dual function capability.
footprint PLCC44_N (Leaded Chip Carrier, 44-Leads, Body 16.6x16.6mm, Pitch 1.27mm, IPC Medium Density)
footprint PLCC44_L (Leaded Chip Carrier, 44-Leads, Body 16.6x16.6mm, Pitch 1.27mm, IPC High Density)
footprint PLCC44_M (Leaded Chip Carrier, 44-Leads, Body 16.6x16.6mm, Pitch 1.27mm, IPC Low Density)
3D model 2032-PLCC44 (44-Pin Leaded Chip Carrier 1.27 mm Pitch)
pins: 1 GND (power), 2 GOE0 (in), 3 I/O24 (io), 4 I/O25 (io), 5 I/O26 (io), 6 I/O27 (io), 7 I/O28 (io), 8 I/O29 (io), 9 I/O30 (io), 10 I/O31 (io), 11 Y0 (in), 12 VCC (power), 13 ~{ispEN} (in), 14 SDI/IN0 (in), 15 I/O0 (io), 16 I/O1 (io), 17 I/O2 (io), 18 I/O3 (io), 19 I/O4 (io), 20 I/O5 (io), 21 I/O6 (io), 22 I/O7 (io), 23 GND (power), 24 SDO/IN1 (io), 25 I/O8 (io), 26 I/O9 (io), 27 I/O10 (io), 28 I/O11 (io), 29 I/O12 (io), 30 I/O13 (io), 31 I/O14 (io), 32 I/O15 (io), 33 Y2/SCLK (in), 34 VCC (power), 35 Y1/~{RESET} (in), 36 MODE (in), 37 I/O16 (io), 38 I/O17 (io), 39 I/O18 (io), 40 I/O19 (io), 41 I/O20 (io), 42 I/O21 (io), 43 I/O22 (io), 44 I/O23 (io)

## ispLSI2032-135LT44
designator U?
In-System Programmable High-Density PLD; Note: Pins 8, 18 and 27 have dual function capability.
footprint TQFP44_N (Thin QFP, 44-Leads, Body 10x10mm, Pitch 0.8mm, IPC Medium Density)
footprint TQFP44_L (Thin QFP, 44-Leads, Body 10x10mm, Pitch 0.8mm, IPC High Density)
footprint TQFP44_M (Thin QFP, 44-Leads, Body 10x10mm, Pitch 0.8mm, IPC Low Density)
3D model 2032-TQFP44 (44-Pin Thin Quad Flat Pack 0.8 mm Pitch)
pins: 1 I/O28 (io), 2 I/O29 (io), 3 I/O30 (io), 4 I/O31 (io), 5 Y0 (in), 6 VCC (power), 7 ~{ispEN} (in), 8 SDI/IN0 (in), 9 I/O0 (io), 10 I/O1 (io), 11 I/O2 (io), 12 I/O3 (io), 13 I/O4 (io), 14 I/O5 (io), 15 I/O6 (io), 16 I/O7 (io), 17 GND (power), 18 SDO/IN1 (io), 19 I/O8 (io), 20 I/O9 (io), 21 I/O10 (io), 22 I/O11 (io), 23 I/O12 (io), 24 I/O13 (io), 25 I/O14 (io), 26 I/O15 (io), 27 Y2/SCLK (in), 28 VCC (power), 29 Y1/~{RESET} (in), 30 MODE (in), 31 I/O16 (io), 32 I/O17 (io), 33 I/O18 (io), 34 I/O19 (io), 35 I/O20 (io), 36 I/O21 (io), 37 I/O22 (io), 38 I/O23 (io), 39 GND (power), 40 GOE0 (in), 41 I/O24 (io), 42 I/O25 (io), 43 I/O26 (io), 44 I/O27 (io)

## ispLSI2032-135LT48
designator U?
In-System Programmable High-Density PLD; Note: Pins 8, 19 and 29 have dual function capability.
footprint TQFP48_N (Thin QFP, 48-Leads, Body 7x7mm, Pitch 0.5mm, IPC Medium Density)
footprint TQFP48_L (Thin QFP, 48-Leads, Body 7x7mm, Pitch 0.5mm, IPC High Density)
footprint TQFP48_M (Thin QFP, 48-Leads, Body 7x7mm, Pitch 0.5mm, IPC Low Density)
3D model 2032-TQFP48 (48-Pin Thin Quad Flat Pack 0.5 mm Pitch)
pins: 1 I/O28 (io), 2 I/O29 (io), 3 I/O30 (io), 4 I/O31 (io), 5 Y0 (in), 6 VCC (power), 7 ~{ispEN} (in), 8 SDI/IN0 (in), 9 I/O0 (io), 10 I/O1 (io), 11 I/O2 (io), 12 NC, 13 I/O3 (io), 14 I/O4 (io), 15 I/O5 (io), 16 I/O6 (io), 17 I/O7 (io), 18 GND (power), 19 SDO/IN1 (io), 20 I/O8 (io), 21 I/O9 (io), 22 I/O10 (io), 23 I/O11 (io), 24 NC, 25 I/O12 (io), 26 I/O13 (io), 27 I/O14 (io), 28 I/O15 (io), 29 Y2/SCLK (in), 30 VCC (power), 31 Y1/~{RESET} (in), 32 MODE (in), 33 I/O16 (io), 34 I/O17 (io), 35 I/O18 (io), 36 NC, 37 I/O19 (io), 38 I/O20 (io), 39 I/O21 (io), 40 I/O22 (io), 41 I/O23 (io), 42 GND (power), 43 GOE0 (in), 44 I/O24 (io), 45 I/O25 (io), 46 I/O26 (io), 47 I/O27 (io), 48 NC

## ispLSI2032-150LJ
designator U?
In-System Programmable High-Density PLD; Note: Pins 14, 24 and 33 have dual function capability.
footprint PLCC44_N (Leaded Chip Carrier, 44-Leads, Body 16.6x16.6mm, Pitch 1.27mm, IPC Medium Density)
footprint PLCC44_L (Leaded Chip Carrier, 44-Leads, Body 16.6x16.6mm, Pitch 1.27mm, IPC High Density)
footprint PLCC44_M (Leaded Chip Carrier, 44-Leads, Body 16.6x16.6mm, Pitch 1.27mm, IPC Low Density)
3D model 2032-PLCC44 (44-Pin Leaded Chip Carrier 1.27 mm Pitch)
pins: 1 GND (power), 2 GOE0 (in), 3 I/O24 (io), 4 I/O25 (io), 5 I/O26 (io), 6 I/O27 (io), 7 I/O28 (io), 8 I/O29 (io), 9 I/O30 (io), 10 I/O31 (io), 11 Y0 (in), 12 VCC (power), 13 ~{ispEN} (in), 14 SDI/IN0 (in), 15 I/O0 (io), 16 I/O1 (io), 17 I/O2 (io), 18 I/O3 (io), 19 I/O4 (io), 20 I/O5 (io), 21 I/O6 (io), 22 I/O7 (io), 23 GND (power), 24 SDO/IN1 (io), 25 I/O8 (io), 26 I/O9 (io), 27 I/O10 (io), 28 I/O11 (io), 29 I/O12 (io), 30 I/O13 (io), 31 I/O14 (io), 32 I/O15 (io), 33 Y2/SCLK (in), 34 VCC (power), 35 Y1/~{RESET} (in), 36 MODE (in), 37 I/O16 (io), 38 I/O17 (io), 39 I/O18 (io), 40 I/O19 (io), 41 I/O20 (io), 42 I/O21 (io), 43 I/O22 (io), 44 I/O23 (io)

## ispLSI2032-150LT44
designator U?
In-System Programmable High-Density PLD; Note: Pins 8, 18 and 27 have dual function capability.
footprint TQFP44_N (Thin QFP, 44-Leads, Body 10x10mm, Pitch 0.8mm, IPC Medium Density)
footprint TQFP44_L (Thin QFP, 44-Leads, Body 10x10mm, Pitch 0.8mm, IPC High Density)
footprint TQFP44_M (Thin QFP, 44-Leads, Body 10x10mm, Pitch 0.8mm, IPC Low Density)
3D model 2032-TQFP44 (44-Pin Thin Quad Flat Pack 0.8 mm Pitch)
pins: 1 I/O28 (io), 2 I/O29 (io), 3 I/O30 (io), 4 I/O31 (io), 5 Y0 (in), 6 VCC (power), 7 ~{ispEN} (in), 8 SDI/IN0 (in), 9 I/O0 (io), 10 I/O1 (io), 11 I/O2 (io), 12 I/O3 (io), 13 I/O4 (io), 14 I/O5 (io), 15 I/O6 (io), 16 I/O7 (io), 17 GND (power), 18 SDO/IN1 (io), 19 I/O8 (io), 20 I/O9 (io), 21 I/O10 (io), 22 I/O11 (io), 23 I/O12 (io), 24 I/O13 (io), 25 I/O14 (io), 26 I/O15 (io), 27 Y2/SCLK (in), 28 VCC (power), 29 Y1/~{RESET} (in), 30 MODE (in), 31 I/O16 (io), 32 I/O17 (io), 33 I/O18 (io), 34 I/O19 (io), 35 I/O20 (io), 36 I/O21 (io), 37 I/O22 (io), 38 I/O23 (io), 39 GND (power), 40 GOE0 (in), 41 I/O24 (io), 42 I/O25 (io), 43 I/O26 (io), 44 I/O27 (io)

## ispLSI2032-150LT48
designator U?
In-System Programmable High-Density PLD; Note: Pins 8, 19 and 29 have dual function capability.
footprint TQFP48_N (Thin QFP, 48-Leads, Body 7x7mm, Pitch 0.5mm, IPC Medium Density)
footprint TQFP48_L (Thin QFP, 48-Leads, Body 7x7mm, Pitch 0.5mm, IPC High Density)
footprint TQFP48_M (Thin QFP, 48-Leads, Body 7x7mm, Pitch 0.5mm, IPC Low Density)
3D model 2032-TQFP48 (48-Pin Thin Quad Flat Pack 0.5 mm Pitch)
pins: 1 I/O28 (io), 2 I/O29 (io), 3 I/O30 (io), 4 I/O31 (io), 5 Y0 (in), 6 VCC (power), 7 ~{ispEN} (in), 8 SDI/IN0 (in), 9 I/O0 (io), 10 I/O1 (io), 11 I/O2 (io), 12 NC, 13 I/O3 (io), 14 I/O4 (io), 15 I/O5 (io), 16 I/O6 (io), 17 I/O7 (io), 18 GND (power), 19 SDO/IN1 (io), 20 I/O8 (io), 21 I/O9 (io), 22 I/O10 (io), 23 I/O11 (io), 24 NC, 25 I/O12 (io), 26 I/O13 (io), 27 I/O14 (io), 28 I/O15 (io), 29 Y2/SCLK (in), 30 VCC (power), 31 Y1/~{RESET} (in), 32 MODE (in), 33 I/O16 (io), 34 I/O17 (io), 35 I/O18 (io), 36 NC, 37 I/O19 (io), 38 I/O20 (io), 39 I/O21 (io), 40 I/O22 (io), 41 I/O23 (io), 42 GND (power), 43 GOE0 (in), 44 I/O24 (io), 45 I/O25 (io), 46 I/O26 (io), 47 I/O27 (io), 48 NC

## ispLSI2032-180LJ
designator U?
In-System Programmable High-Density PLD; Note: Pins 14, 24 and 33 have dual function capability.
footprint PLCC44_N (Leaded Chip Carrier, 44-Leads, Body 16.6x16.6mm, Pitch 1.27mm, IPC Medium Density)
footprint PLCC44_L (Leaded Chip Carrier, 44-Leads, Body 16.6x16.6mm, Pitch 1.27mm, IPC High Density)
footprint PLCC44_M (Leaded Chip Carrier, 44-Leads, Body 16.6x16.6mm, Pitch 1.27mm, IPC Low Density)
3D model 2032-PLCC44 (44-Pin Leaded Chip Carrier 1.27 mm Pitch)
pins: 1 GND (power), 2 GOE0 (in), 3 I/O24 (io), 4 I/O25 (io), 5 I/O26 (io), 6 I/O27 (io), 7 I/O28 (io), 8 I/O29 (io), 9 I/O30 (io), 10 I/O31 (io), 11 Y0 (in), 12 VCC (power), 13 ~{ispEN} (in), 14 SDI/IN0 (in), 15 I/O0 (io), 16 I/O1 (io), 17 I/O2 (io), 18 I/O3 (io), 19 I/O4 (io), 20 I/O5 (io), 21 I/O6 (io), 22 I/O7 (io), 23 GND (power), 24 SDO/IN1 (io), 25 I/O8 (io), 26 I/O9 (io), 27 I/O10 (io), 28 I/O11 (io), 29 I/O12 (io), 30 I/O13 (io), 31 I/O14 (io), 32 I/O15 (io), 33 Y2/SCLK (in), 34 VCC (power), 35 Y1/~{RESET} (in), 36 MODE (in), 37 I/O16 (io), 38 I/O17 (io), 39 I/O18 (io), 40 I/O19 (io), 41 I/O20 (io), 42 I/O21 (io), 43 I/O22 (io), 44 I/O23 (io)

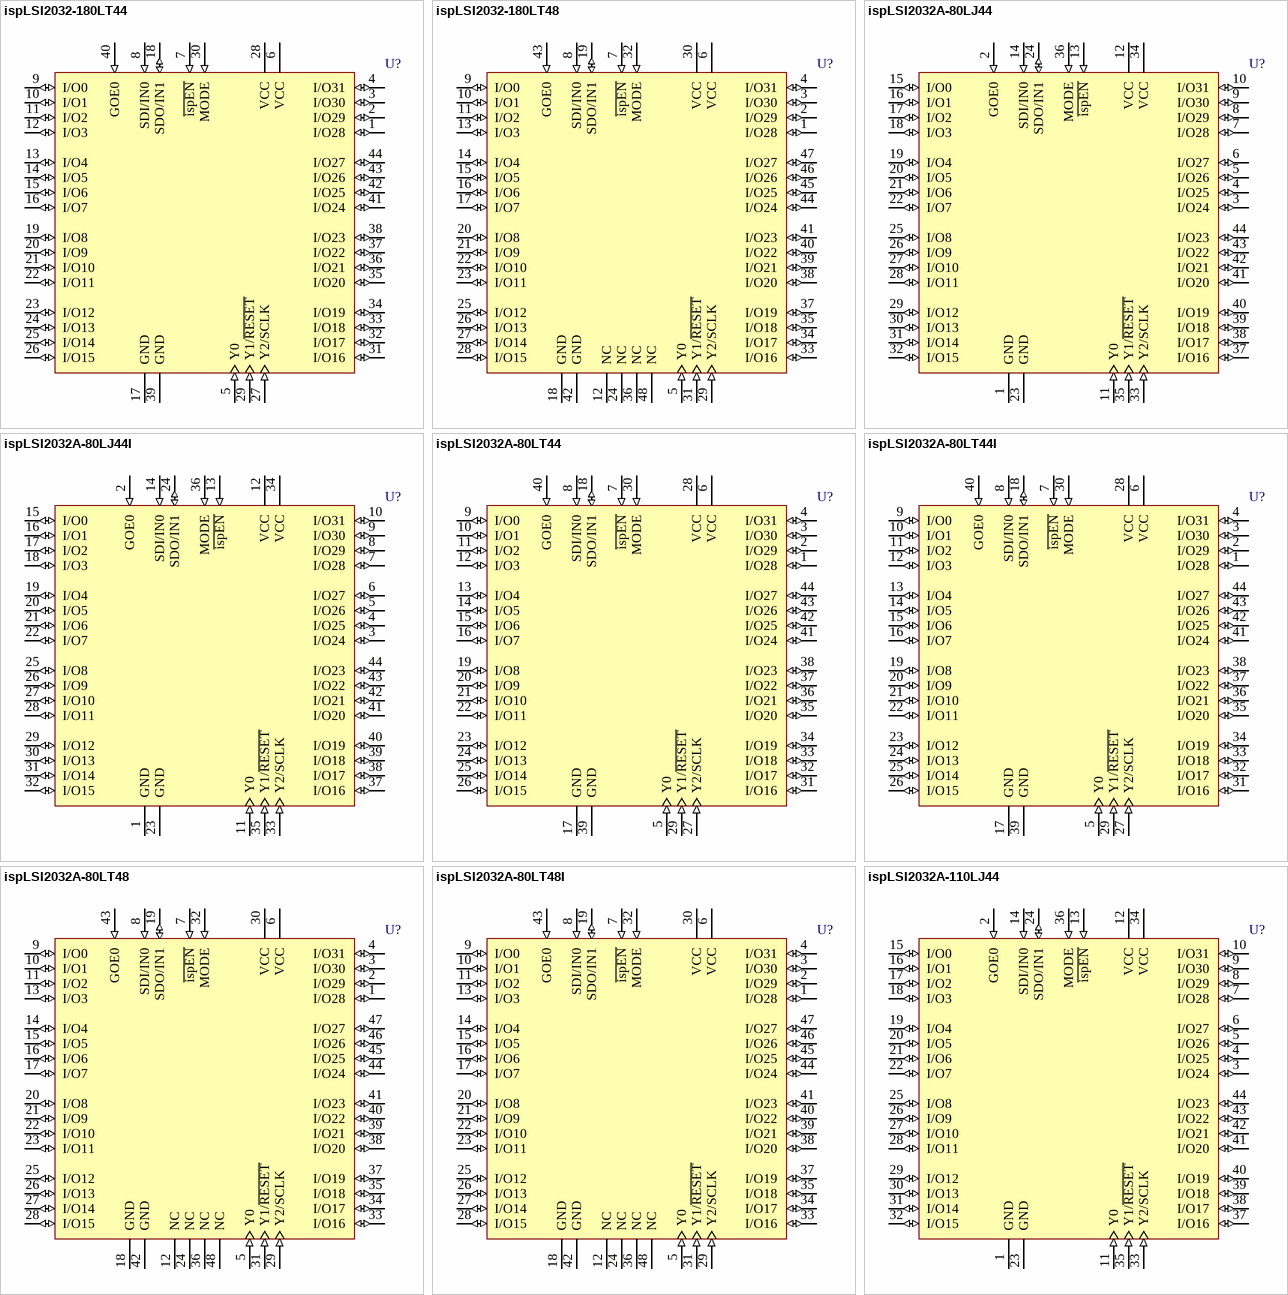
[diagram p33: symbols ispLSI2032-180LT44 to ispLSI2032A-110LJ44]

## ispLSI2032-180LT44
designator U?
In-System Programmable High-Density PLD; Note: Pins 8, 18 and 27 have dual function capability.
footprint TQFP44_N (Thin QFP, 44-Leads, Body 10x10mm, Pitch 0.8mm, IPC Medium Density)
footprint TQFP44_L (Thin QFP, 44-Leads, Body 10x10mm, Pitch 0.8mm, IPC High Density)
footprint TQFP44_M (Thin QFP, 44-Leads, Body 10x10mm, Pitch 0.8mm, IPC Low Density)
3D model 2032-TQFP44 (44-Pin Thin Quad Flat Pack 0.8 mm Pitch)
pins: 1 I/O28 (io), 2 I/O29 (io), 3 I/O30 (io), 4 I/O31 (io), 5 Y0 (in), 6 VCC (power), 7 ~{ispEN} (in), 8 SDI/IN0 (in), 9 I/O0 (io), 10 I/O1 (io), 11 I/O2 (io), 12 I/O3 (io), 13 I/O4 (io), 14 I/O5 (io), 15 I/O6 (io), 16 I/O7 (io), 17 GND (power), 18 SDO/IN1 (io), 19 I/O8 (io), 20 I/O9 (io), 21 I/O10 (io), 22 I/O11 (io), 23 I/O12 (io), 24 I/O13 (io), 25 I/O14 (io), 26 I/O15 (io), 27 Y2/SCLK (in), 28 VCC (power), 29 Y1/~{RESET} (in), 30 MODE (in), 31 I/O16 (io), 32 I/O17 (io), 33 I/O18 (io), 34 I/O19 (io), 35 I/O20 (io), 36 I/O21 (io), 37 I/O22 (io), 38 I/O23 (io), 39 GND (power), 40 GOE0 (in), 41 I/O24 (io), 42 I/O25 (io), 43 I/O26 (io), 44 I/O27 (io)

## ispLSI2032-180LT48
designator U?
In-System Programmable High-Density PLD; Note: Pins 8, 19 and 29 have dual function capability.
footprint TQFP48_N (Thin QFP, 48-Leads, Body 7x7mm, Pitch 0.5mm, IPC Medium Density)
footprint TQFP48_L (Thin QFP, 48-Leads, Body 7x7mm, Pitch 0.5mm, IPC High Density)
footprint TQFP48_M (Thin QFP, 48-Leads, Body 7x7mm, Pitch 0.5mm, IPC Low Density)
3D model 2032-TQFP48 (48-Pin Thin Quad Flat Pack 0.5 mm Pitch)
pins: 1 I/O28 (io), 2 I/O29 (io), 3 I/O30 (io), 4 I/O31 (io), 5 Y0 (in), 6 VCC (power), 7 ~{ispEN} (in), 8 SDI/IN0 (in), 9 I/O0 (io), 10 I/O1 (io), 11 I/O2 (io), 12 NC, 13 I/O3 (io), 14 I/O4 (io), 15 I/O5 (io), 16 I/O6 (io), 17 I/O7 (io), 18 GND (power), 19 SDO/IN1 (io), 20 I/O8 (io), 21 I/O9 (io), 22 I/O10 (io), 23 I/O11 (io), 24 NC, 25 I/O12 (io), 26 I/O13 (io), 27 I/O14 (io), 28 I/O15 (io), 29 Y2/SCLK (in), 30 VCC (power), 31 Y1/~{RESET} (in), 32 MODE (in), 33 I/O16 (io), 34 I/O17 (io), 35 I/O18 (io), 36 NC, 37 I/O19 (io), 38 I/O20 (io), 39 I/O21 (io), 40 I/O22 (io), 41 I/O23 (io), 42 GND (power), 43 GOE0 (in), 44 I/O24 (io), 45 I/O25 (io), 46 I/O26 (io), 47 I/O27 (io), 48 NC

## ispLSI2032A-80LJ44
designator U?
In-System Programmable High-Density PLD; Note: Pins 14, 24 and 33 have dual function capability.
footprint PLCC44_N (Leaded Chip Carrier, 44-Leads, Body 16.6x16.6mm, Pitch 1.27mm, IPC Medium Density)
footprint PLCC44_L (Leaded Chip Carrier, 44-Leads, Body 16.6x16.6mm, Pitch 1.27mm, IPC High Density)
footprint PLCC44_M (Leaded Chip Carrier, 44-Leads, Body 16.6x16.6mm, Pitch 1.27mm, IPC Low Density)
3D model 2032A-PLCC44 (44-Pin Leaded Chip Carrier 1.27 mm Pitch)
pins: 1 GND (power), 2 GOE0 (in), 3 I/O24 (io), 4 I/O25 (io), 5 I/O26 (io), 6 I/O27 (io), 7 I/O28 (io), 8 I/O29 (io), 9 I/O30 (io), 10 I/O31 (io), 11 Y0 (in), 12 VCC (power), 13 ~{ispEN} (in), 14 SDI/IN0 (in), 15 I/O0 (io), 16 I/O1 (io), 17 I/O2 (io), 18 I/O3 (io), 19 I/O4 (io), 20 I/O5 (io), 21 I/O6 (io), 22 I/O7 (io), 23 GND (power), 24 SDO/IN1 (io), 25 I/O8 (io), 26 I/O9 (io), 27 I/O10 (io), 28 I/O11 (io), 29 I/O12 (io), 30 I/O13 (io), 31 I/O14 (io), 32 I/O15 (io), 33 Y2/SCLK (in), 34 VCC (power), 35 Y1/~{RESET} (in), 36 MODE (in), 37 I/O16 (io), 38 I/O17 (io), 39 I/O18 (io), 40 I/O19 (io), 41 I/O20 (io), 42 I/O21 (io), 43 I/O22 (io), 44 I/O23 (io)

## ispLSI2032A-80LJ44I
designator U?
In-System Programmable High-Density PLD; Note: Pins 14, 24 and 33 have dual function capability.
footprint PLCC44_N (Leaded Chip Carrier, 44-Leads, Body 16.6x16.6mm, Pitch 1.27mm, IPC Medium Density)
footprint PLCC44_L (Leaded Chip Carrier, 44-Leads, Body 16.6x16.6mm, Pitch 1.27mm, IPC High Density)
footprint PLCC44_M (Leaded Chip Carrier, 44-Leads, Body 16.6x16.6mm, Pitch 1.27mm, IPC Low Density)
3D model 2032A-PLCC44 (44-Pin Leaded Chip Carrier 1.27 mm Pitch)
pins: 1 GND (power), 2 GOE0 (in), 3 I/O24 (io), 4 I/O25 (io), 5 I/O26 (io), 6 I/O27 (io), 7 I/O28 (io), 8 I/O29 (io), 9 I/O30 (io), 10 I/O31 (io), 11 Y0 (in), 12 VCC (power), 13 ~{ispEN} (in), 14 SDI/IN0 (in), 15 I/O0 (io), 16 I/O1 (io), 17 I/O2 (io), 18 I/O3 (io), 19 I/O4 (io), 20 I/O5 (io), 21 I/O6 (io), 22 I/O7 (io), 23 GND (power), 24 SDO/IN1 (io), 25 I/O8 (io), 26 I/O9 (io), 27 I/O10 (io), 28 I/O11 (io), 29 I/O12 (io), 30 I/O13 (io), 31 I/O14 (io), 32 I/O15 (io), 33 Y2/SCLK (in), 34 VCC (power), 35 Y1/~{RESET} (in), 36 MODE (in), 37 I/O16 (io), 38 I/O17 (io), 39 I/O18 (io), 40 I/O19 (io), 41 I/O20 (io), 42 I/O21 (io), 43 I/O22 (io), 44 I/O23 (io)

## ispLSI2032A-80LT44
designator U?
In-System Programmable High-Density PLD; Note: Pins 8, 18 and 27 have dual function capability.
footprint TQFP44_N (Thin QFP, 44-Leads, Body 10x10mm, Pitch 0.8mm, IPC Medium Density)
footprint TQFP44_L (Thin QFP, 44-Leads, Body 10x10mm, Pitch 0.8mm, IPC High Density)
footprint TQFP44_M (Thin QFP, 44-Leads, Body 10x10mm, Pitch 0.8mm, IPC Low Density)
3D model 2032A-TQFP44 (44-Pin Thin Quad Flat Pack 0.8 mm Pitch)
pins: 1 I/O28 (io), 2 I/O29 (io), 3 I/O30 (io), 4 I/O31 (io), 5 Y0 (in), 6 VCC (power), 7 ~{ispEN} (in), 8 SDI/IN0 (in), 9 I/O0 (io), 10 I/O1 (io), 11 I/O2 (io), 12 I/O3 (io), 13 I/O4 (io), 14 I/O5 (io), 15 I/O6 (io), 16 I/O7 (io), 17 GND (power), 18 SDO/IN1 (io), 19 I/O8 (io), 20 I/O9 (io), 21 I/O10 (io), 22 I/O11 (io), 23 I/O12 (io), 24 I/O13 (io), 25 I/O14 (io), 26 I/O15 (io), 27 Y2/SCLK (in), 28 VCC (power), 29 Y1/~{RESET} (in), 30 MODE (in), 31 I/O16 (io), 32 I/O17 (io), 33 I/O18 (io), 34 I/O19 (io), 35 I/O20 (io), 36 I/O21 (io), 37 I/O22 (io), 38 I/O23 (io), 39 GND (power), 40 GOE0 (in), 41 I/O24 (io), 42 I/O25 (io), 43 I/O26 (io), 44 I/O27 (io)

## ispLSI2032A-80LT44I
designator U?
In-System Programmable High-Density PLD; Note: Pins 8, 18 and 27 have dual function capability.
footprint TQFP44_N (Thin QFP, 44-Leads, Body 10x10mm, Pitch 0.8mm, IPC Medium Density)
footprint TQFP44_L (Thin QFP, 44-Leads, Body 10x10mm, Pitch 0.8mm, IPC High Density)
footprint TQFP44_M (Thin QFP, 44-Leads, Body 10x10mm, Pitch 0.8mm, IPC Low Density)
3D model 2032A-TQFP44 (44-Pin Thin Quad Flat Pack 0.8 mm Pitch)
pins: 1 I/O28 (io), 2 I/O29 (io), 3 I/O30 (io), 4 I/O31 (io), 5 Y0 (in), 6 VCC (power), 7 ~{ispEN} (in), 8 SDI/IN0 (in), 9 I/O0 (io), 10 I/O1 (io), 11 I/O2 (io), 12 I/O3 (io), 13 I/O4 (io), 14 I/O5 (io), 15 I/O6 (io), 16 I/O7 (io), 17 GND (power), 18 SDO/IN1 (io), 19 I/O8 (io), 20 I/O9 (io), 21 I/O10 (io), 22 I/O11 (io), 23 I/O12 (io), 24 I/O13 (io), 25 I/O14 (io), 26 I/O15 (io), 27 Y2/SCLK (in), 28 VCC (power), 29 Y1/~{RESET} (in), 30 MODE (in), 31 I/O16 (io), 32 I/O17 (io), 33 I/O18 (io), 34 I/O19 (io), 35 I/O20 (io), 36 I/O21 (io), 37 I/O22 (io), 38 I/O23 (io), 39 GND (power), 40 GOE0 (in), 41 I/O24 (io), 42 I/O25 (io), 43 I/O26 (io), 44 I/O27 (io)

## ispLSI2032A-80LT48
designator U?
In-System Programmable High-Density PLD; Note: Pins 8, 19 and 29 have dual function capability.
footprint TQFP48_N (Thin QFP, 48-Leads, Body 7x7mm, Pitch 0.5mm, IPC Medium Density)
footprint TQFP48_L (Thin QFP, 48-Leads, Body 7x7mm, Pitch 0.5mm, IPC High Density)
footprint TQFP48_M (Thin QFP, 48-Leads, Body 7x7mm, Pitch 0.5mm, IPC Low Density)
3D model 2032A-TQFP48 (48-Pin Thin Quad Flat Pack 0.5 mm Pitch)
pins: 1 I/O28 (io), 2 I/O29 (io), 3 I/O30 (io), 4 I/O31 (io), 5 Y0 (in), 6 VCC (power), 7 ~{ispEN} (in), 8 SDI/IN0 (in), 9 I/O0 (io), 10 I/O1 (io), 11 I/O2 (io), 12 NC, 13 I/O3 (io), 14 I/O4 (io), 15 I/O5 (io), 16 I/O6 (io), 17 I/O7 (io), 18 GND (power), 19 SDO/IN1 (io), 20 I/O8 (io), 21 I/O9 (io), 22 I/O10 (io), 23 I/O11 (io), 24 NC, 25 I/O12 (io), 26 I/O13 (io), 27 I/O14 (io), 28 I/O15 (io), 29 Y2/SCLK (in), 30 VCC (power), 31 Y1/~{RESET} (in), 32 MODE (in), 33 I/O16 (io), 34 I/O17 (io), 35 I/O18 (io), 36 NC, 37 I/O19 (io), 38 I/O20 (io), 39 I/O21 (io), 40 I/O22 (io), 41 I/O23 (io), 42 GND (power), 43 GOE0 (in), 44 I/O24 (io), 45 I/O25 (io), 46 I/O26 (io), 47 I/O27 (io), 48 NC

## ispLSI2032A-80LT48I
designator U?
In-System Programmable High-Density PLD; Note: Pins 8, 19 and 29 have dual function capability.
footprint TQFP48_N (Thin QFP, 48-Leads, Body 7x7mm, Pitch 0.5mm, IPC Medium Density)
footprint TQFP48_L (Thin QFP, 48-Leads, Body 7x7mm, Pitch 0.5mm, IPC High Density)
footprint TQFP48_M (Thin QFP, 48-Leads, Body 7x7mm, Pitch 0.5mm, IPC Low Density)
3D model 2032A-TQFP48 (48-Pin Thin Quad Flat Pack 0.5 mm Pitch)
pins: 1 I/O28 (io), 2 I/O29 (io), 3 I/O30 (io), 4 I/O31 (io), 5 Y0 (in), 6 VCC (power), 7 ~{ispEN} (in), 8 SDI/IN0 (in), 9 I/O0 (io), 10 I/O1 (io), 11 I/O2 (io), 12 NC, 13 I/O3 (io), 14 I/O4 (io), 15 I/O5 (io), 16 I/O6 (io), 17 I/O7 (io), 18 GND (power), 19 SDO/IN1 (io), 20 I/O8 (io), 21 I/O9 (io), 22 I/O10 (io), 23 I/O11 (io), 24 NC, 25 I/O12 (io), 26 I/O13 (io), 27 I/O14 (io), 28 I/O15 (io), 29 Y2/SCLK (in), 30 VCC (power), 31 Y1/~{RESET} (in), 32 MODE (in), 33 I/O16 (io), 34 I/O17 (io), 35 I/O18 (io), 36 NC, 37 I/O19 (io), 38 I/O20 (io), 39 I/O21 (io), 40 I/O22 (io), 41 I/O23 (io), 42 GND (power), 43 GOE0 (in), 44 I/O24 (io), 45 I/O25 (io), 46 I/O26 (io), 47 I/O27 (io), 48 NC

## ispLSI2032A-110LJ44
designator U?
In-System Programmable High-Density PLD; Note: Pins 14, 24 and 33 have dual function capability.
footprint PLCC44_N (Leaded Chip Carrier, 44-Leads, Body 16.6x16.6mm, Pitch 1.27mm, IPC Medium Density)
footprint PLCC44_L (Leaded Chip Carrier, 44-Leads, Body 16.6x16.6mm, Pitch 1.27mm, IPC High Density)
footprint PLCC44_M (Leaded Chip Carrier, 44-Leads, Body 16.6x16.6mm, Pitch 1.27mm, IPC Low Density)
3D model 2032A-PLCC44 (44-Pin Leaded Chip Carrier 1.27 mm Pitch)
pins: 1 GND (power), 2 GOE0 (in), 3 I/O24 (io), 4 I/O25 (io), 5 I/O26 (io), 6 I/O27 (io), 7 I/O28 (io), 8 I/O29 (io), 9 I/O30 (io), 10 I/O31 (io), 11 Y0 (in), 12 VCC (power), 13 ~{ispEN} (in), 14 SDI/IN0 (in), 15 I/O0 (io), 16 I/O1 (io), 17 I/O2 (io), 18 I/O3 (io), 19 I/O4 (io), 20 I/O5 (io), 21 I/O6 (io), 22 I/O7 (io), 23 GND (power), 24 SDO/IN1 (io), 25 I/O8 (io), 26 I/O9 (io), 27 I/O10 (io), 28 I/O11 (io), 29 I/O12 (io), 30 I/O13 (io), 31 I/O14 (io), 32 I/O15 (io), 33 Y2/SCLK (in), 34 VCC (power), 35 Y1/~{RESET} (in), 36 MODE (in), 37 I/O16 (io), 38 I/O17 (io), 39 I/O18 (io), 40 I/O19 (io), 41 I/O20 (io), 42 I/O21 (io), 43 I/O22 (io), 44 I/O23 (io)

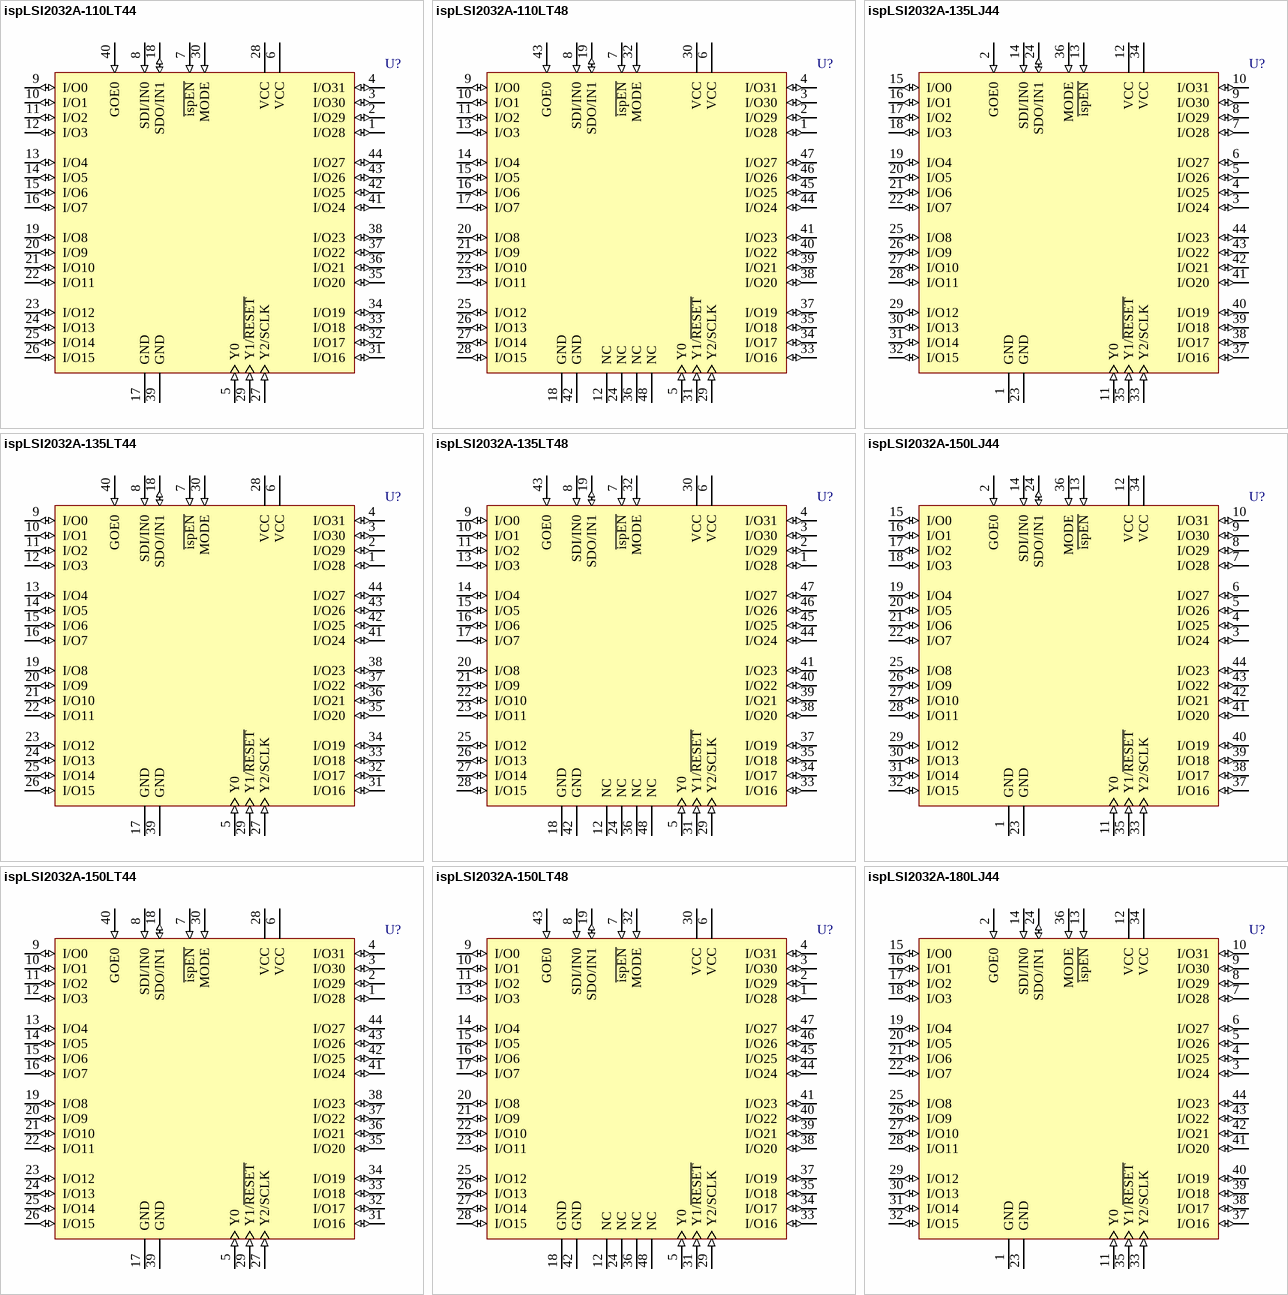
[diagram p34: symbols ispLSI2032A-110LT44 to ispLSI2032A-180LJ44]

## ispLSI2032A-110LT44
designator U?
In-System Programmable High-Density PLD; Note: Pins 8, 18 and 27 have dual function capability.
footprint TQFP44_N (Thin QFP, 44-Leads, Body 10x10mm, Pitch 0.8mm, IPC Medium Density)
footprint TQFP44_L (Thin QFP, 44-Leads, Body 10x10mm, Pitch 0.8mm, IPC High Density)
footprint TQFP44_M (Thin QFP, 44-Leads, Body 10x10mm, Pitch 0.8mm, IPC Low Density)
3D model 2032A-TQFP44 (44-Pin Thin Quad Flat Pack 0.8 mm Pitch)
pins: 1 I/O28 (io), 2 I/O29 (io), 3 I/O30 (io), 4 I/O31 (io), 5 Y0 (in), 6 VCC (power), 7 ~{ispEN} (in), 8 SDI/IN0 (in), 9 I/O0 (io), 10 I/O1 (io), 11 I/O2 (io), 12 I/O3 (io), 13 I/O4 (io), 14 I/O5 (io), 15 I/O6 (io), 16 I/O7 (io), 17 GND (power), 18 SDO/IN1 (io), 19 I/O8 (io), 20 I/O9 (io), 21 I/O10 (io), 22 I/O11 (io), 23 I/O12 (io), 24 I/O13 (io), 25 I/O14 (io), 26 I/O15 (io), 27 Y2/SCLK (in), 28 VCC (power), 29 Y1/~{RESET} (in), 30 MODE (in), 31 I/O16 (io), 32 I/O17 (io), 33 I/O18 (io), 34 I/O19 (io), 35 I/O20 (io), 36 I/O21 (io), 37 I/O22 (io), 38 I/O23 (io), 39 GND (power), 40 GOE0 (in), 41 I/O24 (io), 42 I/O25 (io), 43 I/O26 (io), 44 I/O27 (io)

## ispLSI2032A-110LT48
designator U?
In-System Programmable High-Density PLD; Note: Pins 8, 19 and 29 have dual function capability.
footprint TQFP48_N (Thin QFP, 48-Leads, Body 7x7mm, Pitch 0.5mm, IPC Medium Density)
footprint TQFP48_L (Thin QFP, 48-Leads, Body 7x7mm, Pitch 0.5mm, IPC High Density)
footprint TQFP48_M (Thin QFP, 48-Leads, Body 7x7mm, Pitch 0.5mm, IPC Low Density)
3D model 2032A-TQFP48 (48-Pin Thin Quad Flat Pack 0.5 mm Pitch)
pins: 1 I/O28 (io), 2 I/O29 (io), 3 I/O30 (io), 4 I/O31 (io), 5 Y0 (in), 6 VCC (power), 7 ~{ispEN} (in), 8 SDI/IN0 (in), 9 I/O0 (io), 10 I/O1 (io), 11 I/O2 (io), 12 NC, 13 I/O3 (io), 14 I/O4 (io), 15 I/O5 (io), 16 I/O6 (io), 17 I/O7 (io), 18 GND (power), 19 SDO/IN1 (io), 20 I/O8 (io), 21 I/O9 (io), 22 I/O10 (io), 23 I/O11 (io), 24 NC, 25 I/O12 (io), 26 I/O13 (io), 27 I/O14 (io), 28 I/O15 (io), 29 Y2/SCLK (in), 30 VCC (power), 31 Y1/~{RESET} (in), 32 MODE (in), 33 I/O16 (io), 34 I/O17 (io), 35 I/O18 (io), 36 NC, 37 I/O19 (io), 38 I/O20 (io), 39 I/O21 (io), 40 I/O22 (io), 41 I/O23 (io), 42 GND (power), 43 GOE0 (in), 44 I/O24 (io), 45 I/O25 (io), 46 I/O26 (io), 47 I/O27 (io), 48 NC

## ispLSI2032A-135LJ44
designator U?
In-System Programmable High-Density PLD; Note: Pins 14, 24 and 33 have dual function capability.
footprint PLCC44_N (Leaded Chip Carrier, 44-Leads, Body 16.6x16.6mm, Pitch 1.27mm, IPC Medium Density)
footprint PLCC44_L (Leaded Chip Carrier, 44-Leads, Body 16.6x16.6mm, Pitch 1.27mm, IPC High Density)
footprint PLCC44_M (Leaded Chip Carrier, 44-Leads, Body 16.6x16.6mm, Pitch 1.27mm, IPC Low Density)
3D model 2032A-PLCC44 (44-Pin Leaded Chip Carrier 1.27 mm Pitch)
pins: 1 GND (power), 2 GOE0 (in), 3 I/O24 (io), 4 I/O25 (io), 5 I/O26 (io), 6 I/O27 (io), 7 I/O28 (io), 8 I/O29 (io), 9 I/O30 (io), 10 I/O31 (io), 11 Y0 (in), 12 VCC (power), 13 ~{ispEN} (in), 14 SDI/IN0 (in), 15 I/O0 (io), 16 I/O1 (io), 17 I/O2 (io), 18 I/O3 (io), 19 I/O4 (io), 20 I/O5 (io), 21 I/O6 (io), 22 I/O7 (io), 23 GND (power), 24 SDO/IN1 (io), 25 I/O8 (io), 26 I/O9 (io), 27 I/O10 (io), 28 I/O11 (io), 29 I/O12 (io), 30 I/O13 (io), 31 I/O14 (io), 32 I/O15 (io), 33 Y2/SCLK (in), 34 VCC (power), 35 Y1/~{RESET} (in), 36 MODE (in), 37 I/O16 (io), 38 I/O17 (io), 39 I/O18 (io), 40 I/O19 (io), 41 I/O20 (io), 42 I/O21 (io), 43 I/O22 (io), 44 I/O23 (io)

## ispLSI2032A-135LT44
designator U?
In-System Programmable High-Density PLD; Note: Pins 8, 18 and 27 have dual function capability.
footprint TQFP44_N (Thin QFP, 44-Leads, Body 10x10mm, Pitch 0.8mm, IPC Medium Density)
footprint TQFP44_L (Thin QFP, 44-Leads, Body 10x10mm, Pitch 0.8mm, IPC High Density)
footprint TQFP44_M (Thin QFP, 44-Leads, Body 10x10mm, Pitch 0.8mm, IPC Low Density)
3D model 2032A-TQFP44 (44-Pin Thin Quad Flat Pack 0.8 mm Pitch)
pins: 1 I/O28 (io), 2 I/O29 (io), 3 I/O30 (io), 4 I/O31 (io), 5 Y0 (in), 6 VCC (power), 7 ~{ispEN} (in), 8 SDI/IN0 (in), 9 I/O0 (io), 10 I/O1 (io), 11 I/O2 (io), 12 I/O3 (io), 13 I/O4 (io), 14 I/O5 (io), 15 I/O6 (io), 16 I/O7 (io), 17 GND (power), 18 SDO/IN1 (io), 19 I/O8 (io), 20 I/O9 (io), 21 I/O10 (io), 22 I/O11 (io), 23 I/O12 (io), 24 I/O13 (io), 25 I/O14 (io), 26 I/O15 (io), 27 Y2/SCLK (in), 28 VCC (power), 29 Y1/~{RESET} (in), 30 MODE (in), 31 I/O16 (io), 32 I/O17 (io), 33 I/O18 (io), 34 I/O19 (io), 35 I/O20 (io), 36 I/O21 (io), 37 I/O22 (io), 38 I/O23 (io), 39 GND (power), 40 GOE0 (in), 41 I/O24 (io), 42 I/O25 (io), 43 I/O26 (io), 44 I/O27 (io)

## ispLSI2032A-135LT48
designator U?
In-System Programmable High-Density PLD; Note: Pins 8, 19 and 29 have dual function capability.
footprint TQFP48_N (Thin QFP, 48-Leads, Body 7x7mm, Pitch 0.5mm, IPC Medium Density)
footprint TQFP48_L (Thin QFP, 48-Leads, Body 7x7mm, Pitch 0.5mm, IPC High Density)
footprint TQFP48_M (Thin QFP, 48-Leads, Body 7x7mm, Pitch 0.5mm, IPC Low Density)
3D model 2032A-TQFP48 (48-Pin Thin Quad Flat Pack 0.5 mm Pitch)
pins: 1 I/O28 (io), 2 I/O29 (io), 3 I/O30 (io), 4 I/O31 (io), 5 Y0 (in), 6 VCC (power), 7 ~{ispEN} (in), 8 SDI/IN0 (in), 9 I/O0 (io), 10 I/O1 (io), 11 I/O2 (io), 12 NC, 13 I/O3 (io), 14 I/O4 (io), 15 I/O5 (io), 16 I/O6 (io), 17 I/O7 (io), 18 GND (power), 19 SDO/IN1 (io), 20 I/O8 (io), 21 I/O9 (io), 22 I/O10 (io), 23 I/O11 (io), 24 NC, 25 I/O12 (io), 26 I/O13 (io), 27 I/O14 (io), 28 I/O15 (io), 29 Y2/SCLK (in), 30 VCC (power), 31 Y1/~{RESET} (in), 32 MODE (in), 33 I/O16 (io), 34 I/O17 (io), 35 I/O18 (io), 36 NC, 37 I/O19 (io), 38 I/O20 (io), 39 I/O21 (io), 40 I/O22 (io), 41 I/O23 (io), 42 GND (power), 43 GOE0 (in), 44 I/O24 (io), 45 I/O25 (io), 46 I/O26 (io), 47 I/O27 (io), 48 NC

## ispLSI2032A-150LJ44
designator U?
In-System Programmable High-Density PLD; Note: Pins 14, 24 and 33 have dual function capability.
footprint PLCC44_N (Leaded Chip Carrier, 44-Leads, Body 16.6x16.6mm, Pitch 1.27mm, IPC Medium Density)
footprint PLCC44_L (Leaded Chip Carrier, 44-Leads, Body 16.6x16.6mm, Pitch 1.27mm, IPC High Density)
footprint PLCC44_M (Leaded Chip Carrier, 44-Leads, Body 16.6x16.6mm, Pitch 1.27mm, IPC Low Density)
3D model 2032A-PLCC44 (44-Pin Leaded Chip Carrier 1.27 mm Pitch)
pins: 1 GND (power), 2 GOE0 (in), 3 I/O24 (io), 4 I/O25 (io), 5 I/O26 (io), 6 I/O27 (io), 7 I/O28 (io), 8 I/O29 (io), 9 I/O30 (io), 10 I/O31 (io), 11 Y0 (in), 12 VCC (power), 13 ~{ispEN} (in), 14 SDI/IN0 (in), 15 I/O0 (io), 16 I/O1 (io), 17 I/O2 (io), 18 I/O3 (io), 19 I/O4 (io), 20 I/O5 (io), 21 I/O6 (io), 22 I/O7 (io), 23 GND (power), 24 SDO/IN1 (io), 25 I/O8 (io), 26 I/O9 (io), 27 I/O10 (io), 28 I/O11 (io), 29 I/O12 (io), 30 I/O13 (io), 31 I/O14 (io), 32 I/O15 (io), 33 Y2/SCLK (in), 34 VCC (power), 35 Y1/~{RESET} (in), 36 MODE (in), 37 I/O16 (io), 38 I/O17 (io), 39 I/O18 (io), 40 I/O19 (io), 41 I/O20 (io), 42 I/O21 (io), 43 I/O22 (io), 44 I/O23 (io)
